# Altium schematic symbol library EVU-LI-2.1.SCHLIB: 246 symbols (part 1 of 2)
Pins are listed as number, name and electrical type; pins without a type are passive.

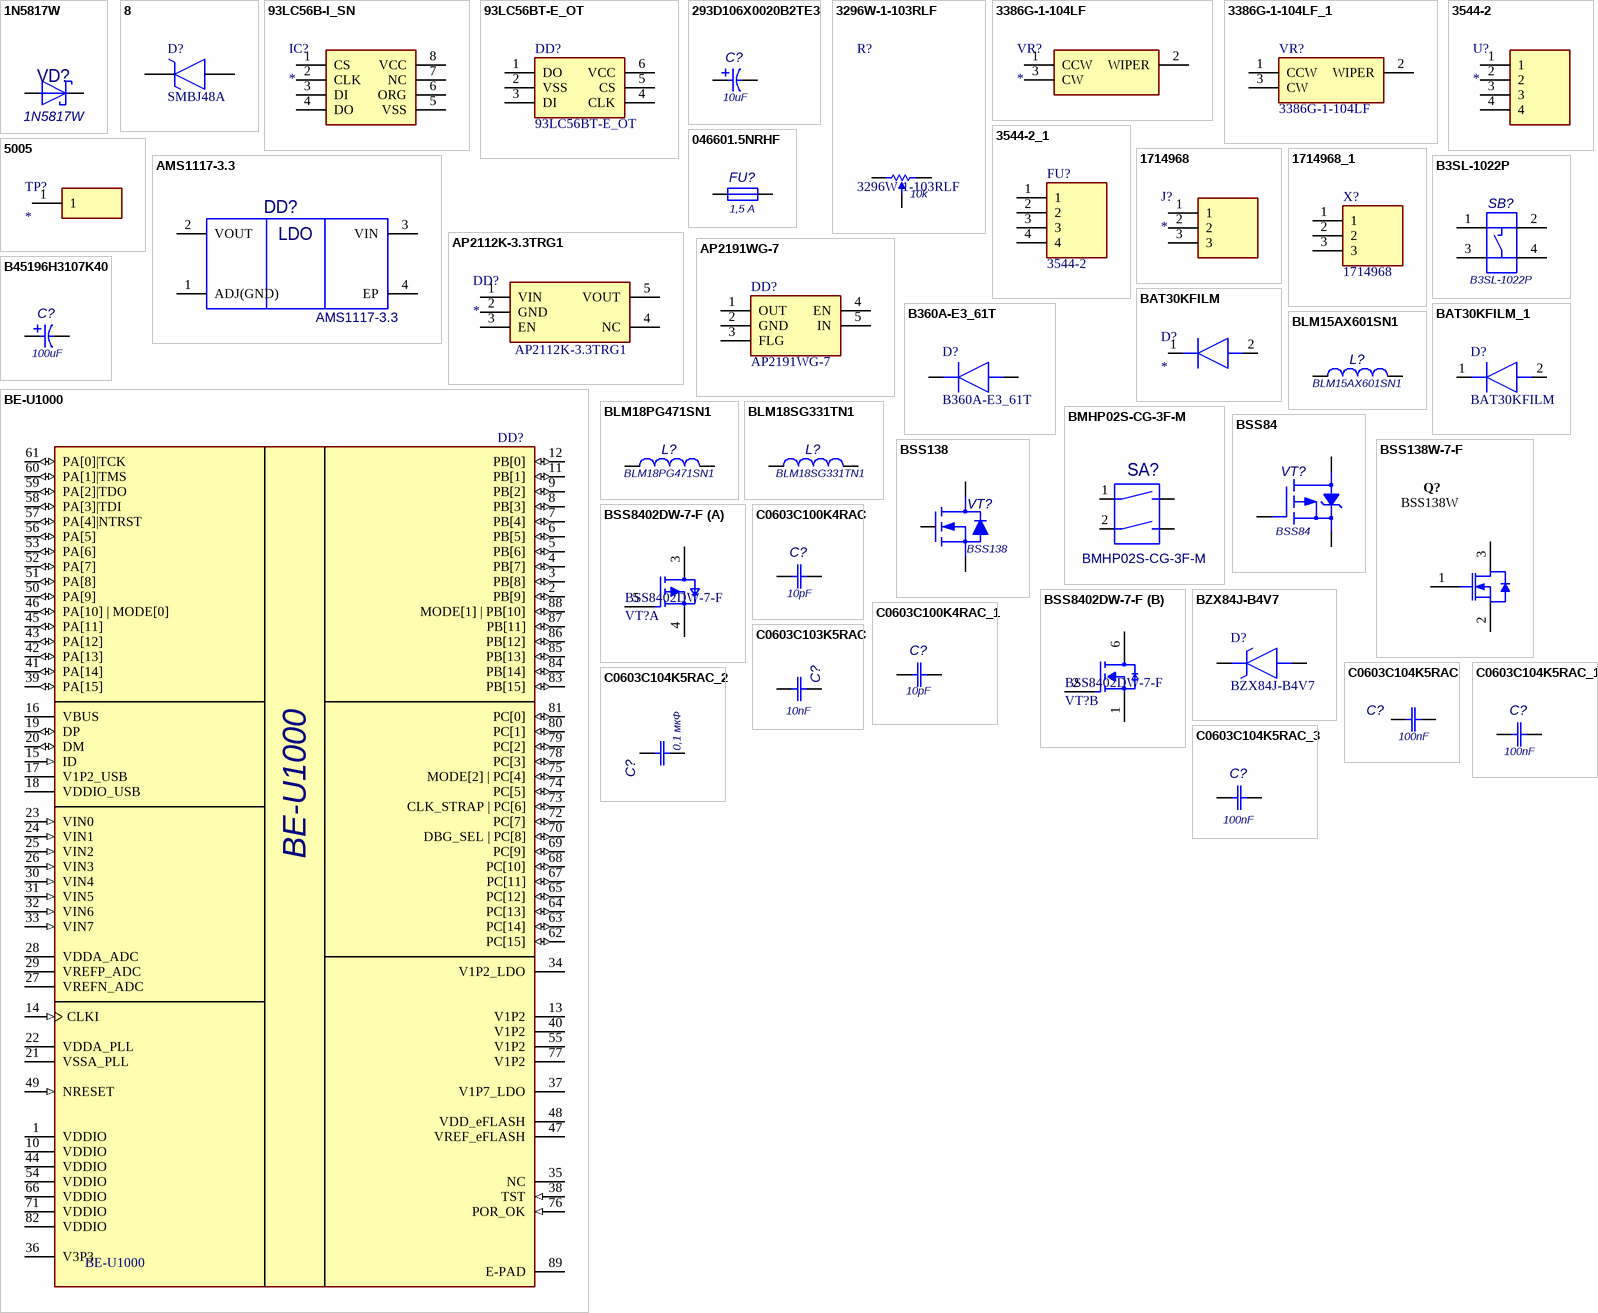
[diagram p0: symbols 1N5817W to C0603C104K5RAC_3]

## 1N5817W
designator VD?
Diode Schottky 20V 1A [SOD-123]; Manufacturer: HOTTECH ELECTRONICS; ESKDname: * 1N5817W, *
footprint DIOD_SMA (Package DO-214AC)
footprint DIOD_SOD-123
footprint DIOD_SOD-123
footprint DIOD_SOD-123W
footprint NSR10F20NXT5G
footprint DIOD_2-XDFN
footprint DIOD_SMF
footprint SOD-323
footprint DIOD_SMB_Flat
footprint DIOD_SMB
pins: A, C

## 8
designator D?, comment SMBJ48A
TVS Diode (Uni-directional); Manufacturer_Name: LITTELFUSE; Manufacturer_Part_Number: SMBJ51A
footprint DIOM5436X261N
footprint Model Name (Footprint not found)
pins: 1 K, 2 A

## 93LC56B-I_SN
designator IC?
Integrated Circuit; Manufacturer_Name: Microchip; Manufacturer_Part_Number: 93LC56B-I/SN
footprint SOIC127P600X175-8N
pins: 1 CS, 2 CLK, 3 DI, 4 DO, 5 VSS, 6 ORG, 7 NC, 8 VCC

## 93LC56BT-E_OT
designator DD?
EEPROM, 2KBIT, SERIAL, 2MHz; Manufacturer_Part_Number: 93LC56BT-E/OT; Manufacturer: "Microchip"; TKE: SOT-23-6
footprint SOT95P270X145-6N
footprint SOT95P280X145-6N
pins: 1 DO, 2 VSS, 3 DI, 4 CLK, 5 CS, 6 VCC

## 293D106X0020B2TE3
designator C?  value 10uF  (hidden comment: 293D106X0020B2TE3)
10uF±20% 20V, Tant type B; Manufacturer: "Vishay"; Tolerance: ±20%; NOM: Type B 10uF ±20% 20V; TKE: Type B; Value Ru: 10мкФ
footprint CAPPM3528X210N
pins: 1, 2

## 3296W-1-103RLF
designator R?  value 10k
Trimmer Resistor 10 kOhms±10% 0,5W; Manufacturer_Name: Bourns; Manufacturer: "Bourns"; Value Ru: 10 кОм; TKE: 3296Y; Power_Voltage: 0,5W; Tolerance: ±10%
footprint 3296W1503LF
footprint 3296W1503LF
pins: 1 CCW, 2 WIPER, 3 CW

## 3386G-1-104LF
designator VR?
Variable Resistor; Manufacturer_Name: Bourns; Manufacturer_Part_Number: 3386G-1-104LF
footprint 3386G1104LF
pins: 1 CCW, 2 WIPER, 3 CW

## 3386G-1-104LF_1
designator VR?, comment 3386G-1-104LF
Variable Resistor; Manufacturer_Name: Bourns
footprint 3386G1104LF
pins: 1 CCW, 2 WIPER, 3 CW

## 3544-2
designator U?
Undefined or Miscellaneous; Manufacturer_Name: Keystone Electronics; Manufacturer_Part_Number: 3544-2
footprint 3544-2
pins: 1, 2, 3, 4

## 3544-2_1
designator FU?, comment 3544-2
Automotive Blade Fuse Holder 20A 500V; Manufacturer: "Keystone Electronics"; Примечание: Fuse Size 2.8mm x 0.8mm
footprint 3544-2
pins: 1, 2, 3, 4

## 5005
designator TP?
Test Point; Manufacturer_Name: Keystone Electronics; Manufacturer_Part_Number: 5005; Manufacturer: "Keystone Electronics"
footprint 5006
pins: 1

## 046601.5NRHF
designator FU?  value 1,5 A  (hidden comment: 046601.5NRHF)
Fuse SMD 1,5A 63V; Manufacturer: "Littelfuse"; MARK: K
footprint FUSE466X32X15X60N
pins: 1, 2

## 1714968
designator J?
Connector; Manufacturer_Name: Phoenix Contact; Manufacturer_Part_Number: 1714968
footprint 1714968
pins: 1, 2, 3

## 1714968_1
designator X?, comment 1714968
PC terminal block, Screw connection, Pitch: 6.35 mm; Manufacturer_Name: Phoenix Contact; Manufacturer: "Phoenix Contact"; Power_Voltage: 500V 30A
footprint 1714968
footprint 1714968
pins: 1, 2, 3

## AMS1117-3.3
designator DD?
1000mA Linear Voltage Regulators; Manufacturer: UMW; ESKDname: Преобразователь напряжения линейный AMS1117-3.3, *
footprint SOT-223
footprint SOT-89 (Small Outline Transistor)
footprint SOT-223
pins: 1 ADJ(GND), 2 VOUT, 3 VIN, 4 EP

## AP2112K-3.3TRG1
designator DD?  Manufacturer_Part_Number: AP2112K-3.3TRG1
LDO voltage regulator; Manufacturer_Name: Diodes Incorporated; Manufacturer: "Diodes"
footprint SOT95P285X140-5N
pins: 1 VIN, 2 GND, 3 EN, 4 NC, 5 VOUT

## AP2191WG-7
designator DD?
Power switch, USB switch, 1.5A; Manufacturer: "Diodes Incorporated"
footprint SOT95P285X140-5N
pins: 1 OUT, 2 GND, 3 FLG, 4 EN, 5 IN

## B3SL-1022P
designator SB?
Surface-mounting Sealed Tactile Switch; Manufacturer: "Omron Corporation"
footprint B3SL-1022P
pins: 1, 2, 3, 4

## B360A-E3_61T
designator D?
Schottky Diode  60V 3.0A; Manufacturer: "Vishay"; Manufacturer_Part_Number: B360A-E3/61T
footprint DIOM5127X229N
pins: 1 K, 2 A

## B45196H3107K40
designator C?  value 100uF  (hidden comment: B45196H3107K40)
100uF±10% 16V, Tant type D; Manufacturer: "Kemet"; Tolerance: ±10%; NOM: Type D 100uF ±10% 16V; TKE: Type D; Value Ru: 100 мкФ
footprint CAPMP7343X190N
pins: 1, 2

## BAT30KFILM
designator D?
Diode; Manufacturer_Name: STMicroelectronics; Manufacturer_Part_Number: BAT30KFILM
footprint SODFL1608X70N
pins: 1 K, 2 A

## BAT30KFILM_1
designator D?, comment BAT30KFILM
Diode; Manufacturer: "STMicroelectronics"; TKE: SOD-523; Power_Voltage: Vrrm 30V Ctyp 14pF if 300mA
footprint SODFL1608X70N
pins: 1 K, 2 A

## BE-U1000
designator DD?
Microcontroller BE-U1000; Manufacturer: "Baikal Electronics"; TKE: QFN 88
footprint QFNWB10X10-88L-AL
pins: 1 VDDIO (power), 2 PB[9] (io), 3 PB[8] (io), 4 PB[7] (io), 5 PB[6] (io), 6 PB[5] (io), 7 PB[4] (io), 8 PB[3] (io), 9 PB[2] (io), 10 VDDIO (power), 11 PB[1] (io), 12 PB[0] (io), 13 V1P2 (power), 14 CLKI (in), 15 ID (in), 16 VBUS (power), 17 V1P2_USB (power), 18 VDDIO_USB (power), 19 DP (io), 20 DM (io), 21 VSSA_PLL (power), 22 VDDA_PLL (power), 23 VIN0 (in), 24 VIN1 (in), 25 VIN2 (in), 26 VIN3 (in), 27 VREFN_ADC (power), 28 VDDA_ADC (power), 29 VREFP_ADC (power), 30 VIN4 (in), 31 VIN5 (in), 32 VIN6 (in), 33 VIN7 (in), 34 V1P2_LDO (power), 35 NC, 36 V3P3 (power), 37 V1P7_LDO (power), 38 TST (in), 39 PA[15] (io), 40 V1P2 (power), 41 PA[14] (io), 42 PA[13] (io), 43 PA[12] (io), 44 VDDIO (power), 45 PA[11] (io), 46 PA[10] | MODE[0] (io), 47 VREF_eFLASH (power), 48 VDD_eFLASH (power), 49 NRESET (in), 50 PA[9] (io), 51 PA[8] (io), 52 PA[7] (io), 53 PA[6] (io), 54 VDDIO (power), 55 V1P2 (power), 56 PA[5] (io), 57 PA[4]|NTRST (io), 58 PA[3]|TDI (io), 59 PA[2]|TDO (io), 60 PA[1]|TMS (io), 61 PA[0]|TCK (io), 62 PC[15] (io), 63 PC[14] (io), 64 PC[13] (io), 65 PC[12] (io), 66 VDDIO (power), 67 PC[11] (io), 68 PC[10] (io), 69 PC[9] (io), 70 DBG_SEL | PC[8] (io), 71 VDDIO (power), 72 PC[7] (io), 73 CLK_STRAP | PC[6] (io), 74 PC[5] (io), 75 MODE[2] | PC[4] (io), 76 POR_OK (in), 77 V1P2 (power), 78 PC[3] (io), 79 PC[2] (io), 80 PC[1] (io), 81 PC[0] (io), 82 VDDIO (power), 83 PB[15] (io), 84 PB[14] (io), 85 PB[13] (io), 86 PB[12] (io), 87 PB[11] (io), 88 MODE[1] | PB[10] (io), 89 E-PAD (power)

## BLM15AX601SN1
designator L?
600 Ohms/100MHz 0,5A 0,34 Ohms; Manufacturer: "Murata"; Value: 600 Ом/100MГц 0,5A 0,34 Ом
footprint BLM15X10X05X50N
pins: 1, 2

## BLM18PG471SN1
designator L?
470 Ohms/100MHz 1A 0,2 Ohms; Manufacturer: "Murata"; Value Ru: 470 Ом/100MГц 1А 0,2 Ом
footprint BLM18X16X08X60N
pins: 1, 2

## BLM18SG331TN1
designator L?
330 Ohms/100 MHz 1,5A 0,07 Ohms; Manufacturer: "Murata"; Value Ru: 330 Ом/100MГц 1,5А 0,07 Ом
footprint INDC1608X95N
pins: 1, 2

## BMHP02S-CG-3F-M
designator SA?
2 switches in case; Manufacturer: "Gangyuan"; ESKDname: Переключатель BMHP02S-CG-3F-M
footprint A6H-21 (SWITCH SMT 2-WAY)
footprint A6H-21 (SWITCH SMT 2-WAY)
pins: 1, 2, 11, 22

## BSS84
designator VT?
P-MOSFET 50V 130mA SOT-23-3; Manufacturer: "NXP Semiconductors"
footprint SOT95P230X110-3N
pins: 1 G, 2 S, 3 D

## BSS138
designator VT?
N-MOSFET 50V 200mA SOT-23-3; Manufacturer: "Fairchild Semiconductor"
footprint SOT95P230X110-3N (Footprint not found)
pins: 1 G, 2 S, 3 D

## BSS138W-7-F
designator Q?, comment BSS138W
N-Channel SIPMOS Small-Signal-Transistor, 60 V VDS, 0.28 A ID, -55 to 150 degC, PG-SOT-323, Reel, Green; Manufacturer: Infineon; Ptot (max): 0.5Â W; RDS (on) (max) (@4.5V): 6,000 mOhm; VDS (max): 60 V; RDS (on) (max): 3,500 mOhm; VGS(th) (max): 1.4Â V; ID (max): 0.28Â A; RthJA (max): 250 K/W; VGS(th) (min): 0.6Â V; IDpuls (max): 1.12Â A; QG: 1 nC; Green: TRUE
footprint INF-PG-SOT-323_M (SOT3, 3-Leads, Body 2x1.25mm, Pitch 0.65mm, IPC Low Density)
footprint INF-PG-SOT-323_N (SOT3, 3-Leads, Body 2x1.25mm, Pitch 0.65mm, IPC Medium Density)
footprint INF-PG-SOT-323_L (SOT3, 3-Leads, Body 2x1.25mm, Pitch 0.65mm, IPC High Density)
pins: 1 GATE, 2 SOURCE, 3 DRAIN

## BSS8402DW-7-F
designator VT?
MOSFET N/P-CH 60V/50V SC70-6; Manufacturer: Diodes; Drain To Source Voltage: 60/-50V; Threshold Vgs Max: 2.5/-2V; Number Of Channels: 2; Turn On Delay Time: 7/10ns; Turn Off Delay Time: 11/18ns; Depletion Mode: False; Number Of P Channels: 1; Transconductance: 0.08/0.05S; Rthja Max: 625°C/W; Gate To Source Voltage: 20V; Power Dissipation: 200mW; Drain To Source Resistance: 4.4/10Ω; Continuous Drain Current: 115/-130mA; Threshold Vgs Min: 1/-0.8V; Max Junction Temp: +150°C; Automotive Grade: NA; Drain To Source Breakdown Voltage: 70/-50V; Standoff Height: 0mm; Pulse Drain Current: 800mA
footprint FP-SOT363-IPC_A
footprint FP-SOT363-IPC_B
footprint FP-SOT363-IPC_C
footprint FP-SOT363-MFG
footprint FP-SOT363-MFG
part A pins: 3 D2, 4 S2, 5 G2
part B pins: 1 S1, 2 G1, 6 D1

## BZX84J-B4V7
designator D?
Zener Diode; Manufacturer: "Nexperia"
footprint SOD2512X80N
pins: 1 K, 2 A

## C0603C100K4RAC
designator C?  Value_ENG: 10pF  (hidden comment: C0603C100K4RAC)
0603 X7R 10 пФ ±10% 16B; Manufacturer: "Kemet"; Value: 10 пФ
footprint CAPC1608X80N
pins: 1, 2

## C0603C100K4RAC_1
designator C?, comment value 10pF  (hidden comment: C0603C100K4RAC)
0603 X7R 10pF±10% 16V; Manufacturer: "Kemet"; Tolerance: ±10%; Power_Voltage: 16B; NOM: 0603 X7R 10pF ±10% 16B; Value Ru: 10 пФ
footprint CAPC1608X80N
pins: 1, 2

## C0603C103K5RAC
designator C?  value 10nF  (hidden comment: C0603C103K5RAC)
0603 X7R 10nF±10% 50V; Manufacturer: "Kemet"; Tolerance: ±10%; Value Ru: 0,01 мкФ
footprint CAPC1608X80N
pins: 1, 2

## C0603C104K5RAC
designator C?  value 100nF  (hidden comment: C0603C104K5RAC)
0603 X7R 0,1 uF ±10% 50V; Manufacturer: "Kemet"; NOM: 0603 X7R 100nF ±10% 50V; Value Ru: 0,1 мкФ
footprint CAPC1608X80N
pins: 1, 2

## C0603C104K5RAC_1
designator C?, comment Value Eng: 100nF  (hidden comment: C0603C104K5RAC)
0603 X7R 0,1 мкФ ±10% 50В; Manufacturer: "Kemet"; Value: 0,1 мкФ
footprint CAPC1608X80N
pins: 1, 2

## C0603C104K5RAC_2
designator C?, comment value 0,1 мкФ  (hidden comment: C0603C104K5RAC)
0603 X7R 0,1 мкФ ±10% 50В; Manufacturer: "Kemet"
footprint CAPC1608X80N
pins: 1, 2

## C0603C104K5RAC_3
designator C?, comment value 100nF  (hidden comment: C0603C104K5RAC)
0603 X7R 0,1uF±10% 50V; Manufacturer: "Kemet"; Tolerance: ±10%; NOM: 0603 X7R 100nF ±10% 50V; Value Ru: 0,1 мкФ
footprint CAPC1608X80N
pins: 1, 2

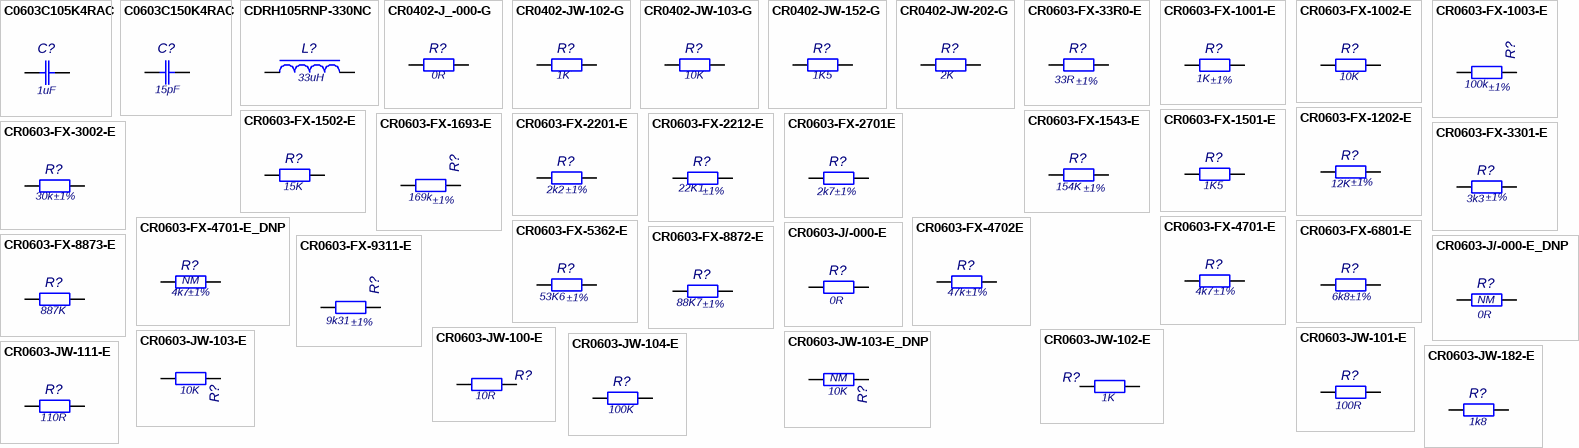
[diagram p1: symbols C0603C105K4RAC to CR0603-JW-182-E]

## C0603C105K4RAC
designator C?  value 1uF  (hidden comment: C0603C105K4RAC)
0603 X7R 1uF±10% 16V; Manufacturer: "Kemet"; Tolerance: ±10%; Value Ru: 1 мкФ
footprint CAPC1608X80N
pins: 1, 2

## C0603C150K4RAC
designator C?  value 15pF  (hidden comment: C0603C150K4RAC)
0603 X7R 15pF±10% 16V; ManufacturerPartNumber: C0603C100K4RAC; Manufacturer: "Kemet"; Tolerance: ±10%; Value Ru: 15 пФ; Replacement: 06035A150JAT2A
footprint CAPC1608X80N
pins: 1, 2

## CDRH105RNP-330NC
designator L?  Value Eng: 33uH  (hidden comment: CDRH105RNP-330NC)
33 uH±30% 2.75A 65mOhm SMD; Manufacturer: "Sumida"; Power_Voltage: 2,4 A; NOM: 33 мкГн  2,4 A; Value: 33 мкГн
footprint CDRH105RNP
pins: 1, 2

## CR0402-J_-000-G
designator R?  value 0R  (hidden comment: CR0402-J_-000-G)
04023 0 Ohm 0.063W; ManufacturerPartNumber: CR0402-J/-000-G; Manufacturer: "Bourns"; Power_Voltage: 0,0625 Вт; MARK: 0; TKE: 0402; NOM: 0402 0R  0,0625 Вт; Value RU: 0 Ом
footprint RESC1005X35N
footprint RESC1005X35N
pins: 1, 2

## CR0402-JW-102-G
designator R?  value 1K  (hidden comment: CR0402-JW-102-G)
0402 1 kOhm ±1% 0.063W; Manufacturer: "Bourns"; Power_Voltage: 0,0625 W; MARK: 102; TKE: 0402; NOM: 0402 1K ±5% 0,0625 W; Tolerance: ±5%; Value Ru: 1 кОм
footprint RESC1005X35N
pins: 1, 2

## CR0402-JW-103-G
designator R?  value 10K  (hidden comment: CR0402-JW-103-G)
0402 10 kOhm ±1% 0.063W; Manufacturer: "Bourns"; Power_Voltage: 0,0625 W; MARK: 103; TKE: 0402; NOM: 0402 10K ±5% 0,0625 W; Tolerance: ±5%; Value Ru: 10 кОм
footprint RESC1005X35N
pins: 1, 2

## CR0402-JW-152-G
designator R?  value 1K5  (hidden comment: CR0402-JW-152-G)
0402 1.5 kOhm ±1% 0.063W; Manufacturer: "Bourns"; Power_Voltage: 0,0625 W; MARK: 152; TKE: 0402; NOM: 0402 1K5 ±5% 0,0625 W; Tolerance: ±5%; Value Ru: 1,5 кОм
footprint RESC1005X35N
pins: 1, 2

## CR0402-JW-202-G
designator R?  value 2K  (hidden comment: CR0402-JW-202-G)
0402 2 kOhm±5% 0.063W; Manufacturer: "Bourns"; Power_Voltage: 0,0625 W; MARK: 202; TKE: 0402; NOM: 0402 2K ±5% 0,0625 W; Tolerance: ±5%; Value Ru: 2 кОм
footprint RESC1005X35N
pins: 1, 2

## CR0603-FX-33R0-E
designator R?  value 33R  Tolerance: ±1%  (hidden comment: CR0603-FX-33R0-E)
0603 33 Ohm±1% 0,1W; Manufacturer: "Bourns"; TKE: 0603; Power_Voltage: 0,1W; NOM: 0603 33R ±1% 0,1W; Value Ru: 33 Ом
footprint RESC1608X45N
pins: 1, 2

## CR0603-FX-1001-E
designator R?  value 1K  Tolerance: ±1%  (hidden comment: CR0603-FX-1001-E)
0603 1 kOhm±1% 0,1W; Manufacturer: "Bourns"; TKE: 0603; MARK: 01B; Power_Voltage: 0,1W; NOM: 0603 1K ±1% 0,1W; Value Ru: 1 кОм
footprint RESC1608X45N
pins: 1, 2

## CR0603-FX-1002-E
designator R?  value 10K  (hidden comment: CR0603-FX-1002-E)
0603 10 kOm±1% 0,1W; Manufacturer: "Bourns"; TKE: 0603; MARK: 01C; Power_Voltage: 0,1 Вт; NOM: 0603 10K ±1% 0,1 Вт; Value Ru: 10 кОм; Tolerance: ±1%
footprint RESC1608X45N
pins: 1, 2

## CR0603-FX-1003-E
designator R?  value 100k  Tolerance: ±1%  (hidden comment: CR0603-FX-1003-E)
0603 100 kOhm±1% 0,1W; ManufacturerPartNumber: CR0603-FX-1693-E; Manufacturer: "Bourns"; TKE: 0603; MARK: 23D; Power_Voltage: 0,1W; NOM: 0603 100k ±1% 0,1W; Value Ru: 100 кОм
footprint RESC1608X45N
pins: 1, 2

## CR0603-FX-1202-E
designator R?  value 12K  Tolerance: ±1%  (hidden comment: CR0603-FX-1202-E)
0603 12 kOhm±1% 0,1W; ManufacturerPartNumber: CR0603-JW-123-E; Manufacturer: "Bourns"; TKE: 0603; MARK: 123; Power_Voltage: 0,1 Вт; NOM: 0603 12K ±1% 0,1 Вт; Value Ru: 12 кОм
footprint RESC1608X45N
pins: 1, 2

## CR0603-FX-1501-E
designator R?  value 1K5  (hidden comment: CR0603-FX-1501-E)
0603 1.5 kOm ±1% 0,1W; Manufacturer: "Bourns"; TKE: 0603; MARK: 18C; Power_Voltage: 0,1 Вт; NOM: 0603 1K5 ±1% 0,1 Вт; Value Ru: 1.5 кОм
footprint RESC1608X45N
pins: 1, 2

## CR0603-FX-1502-E
designator R?  value 15K  (hidden comment: CR0603-FX-1502-E)
0603 15 kOm ±1% 0,1W; Manufacturer: "Bourns"; TKE: 0603; MARK: 18C; Power_Voltage: 0,1 Вт; NOM: 0603 15K ±1% 0,1 Вт; Value Ru: 15 кОм
footprint RESC1608X45N
pins: 1, 2

## CR0603-FX-1543-E
designator R?  value 154K  Tolerance: ±1%  (hidden comment: CR0603-FX-1543-E)
0603 154 kOhm±1% 0,1W; Manufacturer: "Bourns"; TKE: 0603; MARK: 19D; Power_Voltage: 0,1 Вт; NOM: 0603 154K ±1% 0,1 Вт; Value Ru: 154 кОм
footprint RESC1608X45N
pins: 1, 2

## CR0603-FX-1693-E
designator R?  Value Eng: 169k  Tolerance: ±1%  (hidden comment: CR0603-FX-1693-E)
169 кОм ±1%; Manufacturer: "Bourns"; TKE: 0603; MARK: 23D; Power_Voltage: 0,1 Вт; NOM: 0603 169 кОм ±1% 0,1 Вт; Value: 169 кОм
footprint RESC1608X45N
pins: 1, 2

## CR0603-FX-2201-E
designator R?  value 2k2  Tolerance: ±1%  (hidden comment: CR0603-FX-2201-E)
2k2±1%; Manufacturer: "Bourns"; TKE: 0603; MARK: 222; Power_Voltage: 0,1 Вт; NOM: 0603 2k2 ±1% 0,1 Вт; Value Ru: 2,2 кОм
footprint RESC1608X45N
pins: 1, 2

## CR0603-FX-2212-E
designator R?  value 22K1  Tolerance: ±1%  (hidden comment: CR0603-FX-2212-E)
0603 22,1 kOhm±1% 0,1W; Manufacturer: "Bourns"; TKE: 0603; MARK: 34C; Power_Voltage: 0,1 Вт; NOM: 0603 22K1 ±1% 0,1 Вт; Value Ru: 22,1 кОм
footprint RESC1608X45N
pins: 1, 2

## CR0603-FX-2701E
designator R?  value 2k7  Tolerance: ±1%  (hidden comment: CR0603-FX-2701E)
2k7±1%; Manufacturer: "Bourns"; TKE: 0603; Power_Voltage: 0,1W; NOM: 0603 2k7 ±1% 0,1W; Value Ru: 2,7 кОм
footprint RESC1608X45N
pins: 1, 2

## CR0603-FX-3002-E
designator R?  value 30k  Tolerance: ±1%  (hidden comment: CR0603-FX-3002-E)
0603 30 kOhm±1% 0,1W; Manufacturer: "Bourns"; TKE: 0603; Power_Voltage: 0,1W; NOM: 0603 30k ±1% 0,1W; Value Ru: 30 кОм
footprint RESC1608X45N
pins: 1, 2

## CR0603-FX-3301-E
designator R?  value 3k3  Tolerance: ±1%  (hidden comment: CR0603-FX-3301-E)
0603 3,3 kOhm±1% 0,1W; Manufacturer: "Bourns"; TKE: 0603; Power_Voltage: 0,1W; NOM: 0603 3k3 ±1% 0,1W; Value Ru: 3,3 кОм
footprint RESC1608X45N
pins: 1, 2

## CR0603-FX-4701-E
designator R?  value 4k7  Tolerance: ±1%  (hidden comment: CR0603-FX-4701-E)
0603 4,7 kOhm±1% 0,1W; Manufacturer: "Bourns"; TKE: 0603; Power_Voltage: 0,1W; NOM: 0603 4k7 ±1% 0,1W; Value Ru: 4,7 кОм
footprint RESC1608X45N
pins: 1, 2

## CR0603-FX-4701-E_DNP
designator R?, comment value 4k7  Примечание: NM  Tolerance: ±1%  (hidden comment: CR0603-FX-4701-E)
0603 4,7 kOhm±1% 0,1W; Manufacturer: "Bourns"; TKE: 0603; Power_Voltage: 0,1W; NOM: 0603 4k7 ±1% 0,1W; Value Ru: 4,7 кОм
footprint RESC1608X45N
pins: 1, 2

## CR0603-FX-4702E
designator R?  value 47k  Tolerance: ±1%  (hidden comment: CR0603-FX-4702E)
47kOm±1%; Manufacturer: "Bourns"; TKE: 0603; Power_Voltage: 0,1W; NOM: 0603 47k ±1% 0,1W; Value Ru: 47 кОм
footprint RESC1608X45N
pins: 1, 2

## CR0603-FX-5362-E
designator R?  value 53K6  Tolerance: ±1%  (hidden comment: CR0603-FX-5362-E)
0603 53,6 kOhm ±1% 0,1W; Manufacturer: "Bourns"; TKE: 0603; Power_Voltage: 0,1W; NOM: 0603 53K6 ±1% 0,1W; Value Ru: 53,6 кОм
footprint RESC1608X45N
pins: 1, 2

## CR0603-FX-6801-E
designator R?  value 6k8  Tolerance: ±1%  (hidden comment: CR0603-FX-6801-E)
6k8±1%; Manufacturer: "Bourns"; TKE: 0603; Power_Voltage: 0,1W; NOM: 0603 6k8 ±1% 0,1W; Value Ru: 6,8 кОм
footprint RESC1608X45N
pins: 1, 2

## CR0603-FX-8872-E
designator R?  value 88K7  Tolerance: ±1%  (hidden comment: CR0603-FX-8872-E)
0603 88,7 kOhm±1% 0,1W; Manufacturer: "Bourns"; TKE: 0603; Power_Voltage: 0,1W; NOM: 0603 88K7 ±1% 0,1W; Value Ru: 88,7 кОм
footprint RESC1608X45N
pins: 1, 2

## CR0603-FX-8873-E
designator R?  value 887K  (hidden comment: CR0603-FX-8873-E)
0603 887 kOm ±1% 0,1W; Manufacturer: "Bourns"; TKE: 0603; MARK: 92D; Power_Voltage: 0,1 Вт; NOM: 0603 887K ±1% 0,1 Вт; Value Ru: 887 кОм
footprint RESC1608X45N
pins: 1, 2

## CR0603-FX-9311-E
designator R?  Value Eng: 9k31  Tolerance: ±1%  (hidden comment: CR0603-FX-9311-E)
9,31 кОм ±1%; Manufacturer: "Bourns"; TKE: 0603; MARK: 94B; Power_Voltage: 0,1 Вт; NOM: 0603 9,31 кОм ±1% 0,1 Вт
footprint RESC1608X45N
pins: 1, 2

## CR0603-J/-000-E
designator R?  value 0R  (hidden comment: CR0603-J/-000-E)
0603 0 Ohm 0,1W; Manufacturer: "Bourns"; TKE: 0603; MARK: 000; NOM: 0603 0R; Value Ru: 0 Ом; Replacement: RC0603JR-070RL
footprint RESC1608X45N
pins: 1, 2

## CR0603-J/-000-E_DNP
designator R?, comment value 0R  Примечание: NM  (hidden comment: CR0603-J/-000-E)
0603 0 Ohm 0,1W; Manufacturer: "Bourns"; TKE: 0603; MARK: 000; NOM: 0603 0R; Value Ru: 0 Ом
footprint RESC1608X45N
pins: 1, 2

## CR0603-JW-100-E
designator R?  value 10R  (hidden comment: CR0603-JW-100-E)
0603 10 Ohm±5% 0.1W; Manufacturer: "Bourns"; TKE: 0603; MARK: 100; Power_Voltage: 0,1W; NOM: 0603 10R ±5% 0,1W; Tolerance: ±5%; Value Ru: 10 Ом; DNP: NM
footprint RESC1608X45N
pins: 1, 2

## CR0603-JW-101-E
designator R?  value 100R  (hidden comment: CR0603-JW-101-E)
0603 100 Ohm±5% 0,1W; Manufacturer: "Bourns"; TKE: 0603; MARK: 101; Power_Voltage: 0,1W; NOM: 0603 100R ±5% 0,1W; Tolerance: ±5%; Value Ru: 100 Ом
footprint RESC1608X45N
pins: 1, 2

## CR0603-JW-102-E
designator R?  Value Eng: 1K  (hidden comment: CR0603-JW-102-E)
1 кОм , 1K; Manufacturer: "Bourns"; TKE: 0603; MARK: 102; Power_Voltage: 0,1 Вт; NOM: 0603 1 кОм ±5% 0,1 Вт; Tolerance: ±5%; Value: 1 кОм
footprint RESC1608X45N
pins: 1, 2

## CR0603-JW-103-E
designator R?  value 10K  (hidden comment: CR0603-JW-103-E)
0603 10 kOhm±5% 0,1W; Manufacturer: "Bourns"; TKE: 0603; MARK: 103; Power_Voltage: 0,1W; NOM: 0603 10K ±5% 0,1W; Tolerance: ±5%; Value Ru: 10 кОм
footprint RESC1608X45N
pins: 1, 2

## CR0603-JW-103-E_DNP
designator R?, comment value 10K  Примечание: NM  (hidden comment: CR0603-JW-103-E)
0603 10 kOhm±5% 0,1W; Manufacturer: "Bourns"; TKE: 0603; MARK: 103; Power_Voltage: 0,1W; NOM: 0603 10K ±5% 0,1W; Tolerance: ±5%; Value Ru: 10 кОм
footprint RESC1608X45N
pins: 1, 2

## CR0603-JW-104-E
designator R?  value 100K  (hidden comment: CR0603-JW-104-E)
0603 100 kOhm±5% 0.1W; Manufacturer: "Bourns"; TKE: 0603; MARK: 104; Power_Voltage: 0,1 Вт; NOM: 0603 100K ±5% 0,1 Вт; Tolerance: ±5%; Value Ru: 100 кОм
footprint RESC1608X45N
pins: 1, 2

## CR0603-JW-111-E
designator R?  Value Eng: 110R  (hidden comment: CR0603-JW-111-E)
110 Ом , 110R; Manufacturer: "Bourns"; TKE: 0603; MARK: 111; Power_Voltage: 0,1 Вт; NOM: 0603 110 Ом ±5% 0,1 Вт; Tolerance: ±5%; Value: 110 Ом
footprint RESC1608X45N
pins: 1, 2

## CR0603-JW-182-E
designator R?  value 1k8  (hidden comment: CR0603-JW-182-E)
0603 1,8 kOhm±5% 0,1W; Manufacturer: "Bourns"; TKE: 0603; MARK: 182; Power_Voltage: 0,1 Вт; NOM: 0603 1k8 ±5% 0,1 Вт; Tolerance: ±5%; Value Ru: 1,8 кОм
footprint RESC1608X45N
pins: 1, 2

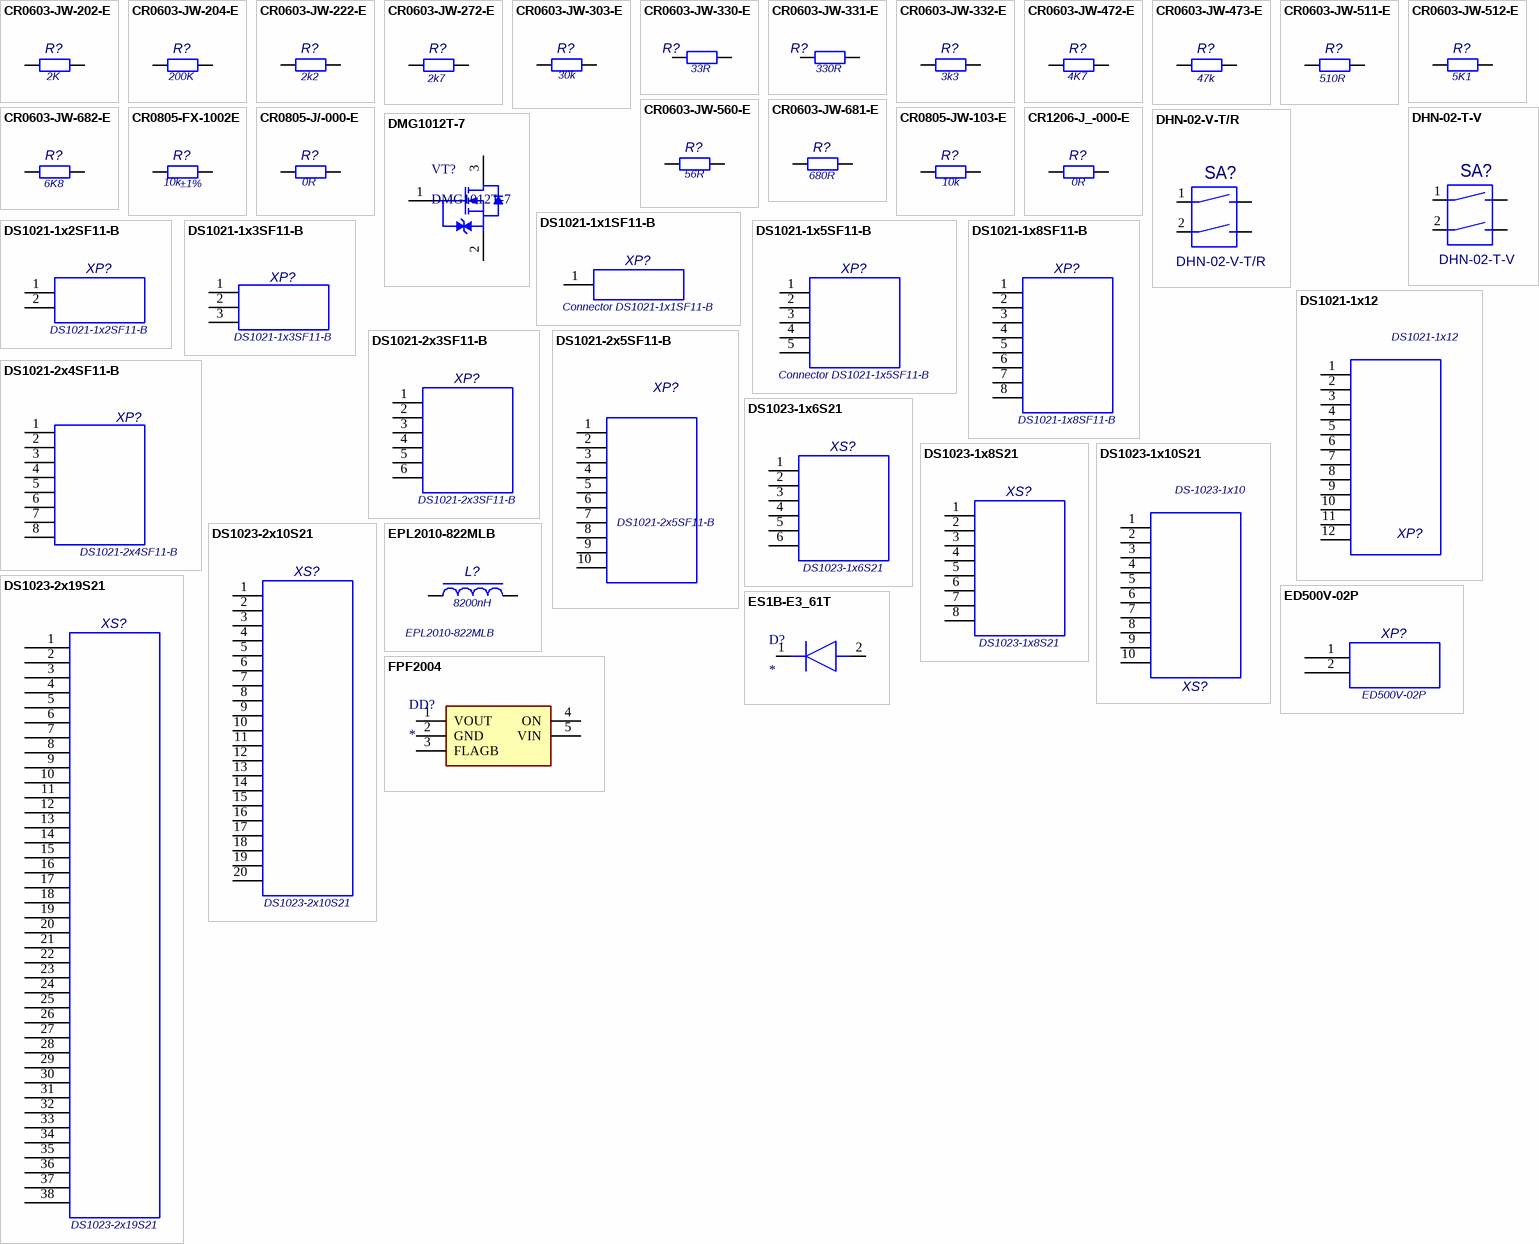
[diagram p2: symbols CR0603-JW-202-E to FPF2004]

## CR0603-JW-202-E
designator R?  value 2K  (hidden comment: CR0603-JW-202-E)
0603 2 kOhm±5% 0.1W; Manufacturer: "Bourns"; TKE: 0603; MARK: 202; Power_Voltage: 0,1 Вт; NOM: 0603 2K ±5% 0,1 Вт; Tolerance: ±5%; Value Ru: 2 кОм
footprint RESC1608X45N
pins: 1, 2

## CR0603-JW-204-E
designator R?  value 200K  (hidden comment: CR0603-JW-204-E)
0603 200 kOm±5% 0.1W; Manufacturer: "Bourns"; TKE: 0603; MARK: 204; Power_Voltage: 0,1 Вт; NOM: 0603 200K ±5% 0,1 Вт; Tolerance: ±5%; Value Ru: 200 кОм
footprint RESC1608X45N
pins: 1, 2

## CR0603-JW-222-E
designator R?  Value Eng: 2k2  (hidden comment: CR0603-JW-222-E)
0603 2,2 kOhm±5% 0,1W; Manufacturer: "Bourns"; TKE: 0603; MARK: 222; Power_Voltage: 0,1W; NOM: 0603 2,2 кОм ±5% 0,1W; Tolerance: ±5%; Value: 2,2 кОм
footprint RESC1608X45N
pins: 1, 2

## CR0603-JW-272-E
designator R?  Value Eng: 2k7  (hidden comment: CR0603-JW-272-E)
0603 2,7 kOhm±5% 0,1W; Manufacturer: "Bourns"; TKE: 0603; MARK: 272; Power_Voltage: 0,1 Вт; NOM: 0603 2,7 кОм ±5% 0,1 Вт; Tolerance: ±5%; Value: 2,7 кОм
footprint RESC1608X45N
pins: 1, 2

## CR0603-JW-303-E
designator R?  Value Eng: 30k  (hidden comment: CR0603-JW-303-E)
0603 30 kOhm±5% 0,1W; Manufacturer: "Bourns"; TKE: 0603; MARK: 303; Power_Voltage: 0,1 Вт; NOM: 0603 30 кОм ±5% 0,1 Вт; Tolerance: ±5%; Value: 30 кОм
footprint RESC1608X45N
pins: 1, 2

## CR0603-JW-330-E
designator R?  value 33R  (hidden comment: CR0603-JW-330-E)
0603 33 Om ±5% 0.1W; Manufacturer: "Bourns"; TKE: 0603; MARK: 330; Power_Voltage: 0,1 Вт; NOM: 0603 33R ±5% 0,1 Вт; Value Ru: 33 Ом
footprint RESC1608X45N
pins: 1, 2

## CR0603-JW-331-E
designator R?  value 330R  (hidden comment: CR0603-JW-331-E)
0603 330 Om ±5% 0.1W; Manufacturer: "Bourns"; TKE: 0603; MARK: 330; Power_Voltage: 0,1 Вт; NOM: 0603 330R ±5% 0,1 Вт; Value Ru: 330 Ом
footprint RESC1608X45N
pins: 1, 2

## CR0603-JW-332-E
designator R?  Value Eng: 3k3  (hidden comment: CR0603-JW-332-E)
3.3 кОм 3k3; Manufacturer: "Bourns"; TKE: 0603; MARK: 332; Power_Voltage: 0,1 Вт; NOM: 0603 3,3 кОм ±5% 0,1 Вт; Tolerance: ±5%; Value: 3,3 кОм
footprint RESC1608X45N
pins: 1, 2

## CR0603-JW-472-E
designator R?  value 4K7  (hidden comment: CR0603-JW-472-E)
0603 4,7 kOm±5% 0.1W; Manufacturer: "Bourns"; TKE: 0603; MARK: 472; Power_Voltage: 0,1 Вт; NOM: 0603 4K7 ±5% 0,1 Вт; Tolerance: ±5%; Value Ru: 4,7 кОм
footprint RESC1608X45N
pins: 1, 2

## CR0603-JW-473-E
designator R?  Value Eng: 47k  (hidden comment: CR0603-JW-473-E)
0603 47 kOhms±5% 0,1W; Manufacturer: "Bourns"; TKE: 0603; MARK: 473; Power_Voltage: 0,1 Вт; NOM: 0603 47 кОм ±5% 0,1 Вт; Tolerance: ±5%; Value: 47 кОм
footprint RESC1608X45N
pins: 1, 2

## CR0603-JW-511-E
designator R?  Value Eng: 510R  (hidden comment: CR0603-JW-511-E)
0603 510 Om ±5% 0.1W; Manufacturer: "Bourns"; TKE: 0603; MARK: 511; Power_Voltage: 0,1 Вт; NOM: 0603 510 Ом ±5% 0,1 Вт; Value: 510 Ом
footprint RESC1608X45N
pins: 1, 2

## CR0603-JW-512-E
designator R?  Value Eng: 5K1  (hidden comment: CR0603-JW-512-E)
0603 5,1 kOhm±5% 0,1W; ManufacturerPartNumber: CR0603-JW-682-E; Manufacturer: "Bourns"; TKE: 0603; MARK: 512; Power_Voltage: 0,1 Вт; NOM: 0603 5,1 кОм ±5% 0,1 Вт; Tolerance: ±5%; Value: 5,1 кОм
footprint RESC1608X45N
pins: 1, 2

## CR0603-JW-560-E
designator R?  value 56R  (hidden comment: CR0603-JW-560-E)
0603 56 Ohm±5% 0,1W; Manufacturer: "Bourns"; TKE: 0603; MARK: 560; Power_Voltage: 0,1W; NOM: 0603 56R ±5% 0,1W; Tolerance: ±5%; Value Ru: 56 Ом
footprint RESC1608X45N
pins: 1, 2

## CR0603-JW-681-E
designator R?  value 680R  (hidden comment: CR0603-JW-681-E)
0603 680 Ohm±5% 0,1W; Manufacturer: "Bourns"; TKE: 0603; MARK: 681; Power_Voltage: 0,1W; NOM: 0603 680R ±5% 0,1W; Tolerance: ±5%; Value Ru: 680 Ом
footprint RESC1608X45N
pins: 1, 2

## CR0603-JW-682-E
designator R?  value 6K8  (hidden comment: CR0603-JW-682-E)
0603 6,8 kOhm±5% 0,1W; Manufacturer: "Bourns"; TKE: 0603; MARK: 682; Power_Voltage: 0,1 Вт; NOM: 0603 6K8 ±5% 0,1 Вт; Tolerance: ±5%; Value Ru: 6,8 кОм
footprint RESC1608X45N
pins: 1, 2

## CR0805-FX-1002E
designator R?  value 10k  Tolerance: ±1%  (hidden comment: CR0805-FX-1002E)
10k±1%; ManufacturerPartNumber: CR0805-JW-103-E; Manufacturer: "Bourns"; TKE: 0805; MARK: 103; Power_Voltage: 0,1 Вт; NOM: 0805 10k ±1% 0,1 Вт; Value Ru: 10 кОм
footprint RESC2012X50N
pins: 1, 2

## CR0805-J/-000-E
designator R?  value 0R  (hidden comment: CR0805-J/-000-E)
0805 0 Ohm 0,1W; Manufacturer: "Bourns"; TKE: 0805; MARK: 000; Power_Voltage: 0,1W; NOM: 0805 0R  0,1W; Value Ru: 0 Ом; DNP: NM
footprint RESC2012X50N
pins: 1, 2

## CR0805-JW-103-E
designator R?  Value Eng: 10k  (hidden comment: CR0805-JW-103-E)
0805 10 kOhm±5% 0,1W; Manufacturer: "Bourns"; TKE: 0805; MARK: 103; Power_Voltage: 0,1W; NOM: 0805 10 кОм ±5% 0,1W; Tolerance: ±5%; Value: 10 кОм
footprint RESC2012X50N
pins: 1, 2

## CR1206-J_-000-E
designator R?  Value Eng: 0R  (hidden comment: CR1206-J_-000-E)
0 Ом 0R; ManufacturerPartNumber: CR1206-J/-000; Manufacturer: "Bourns"; TKE: 1206; MARK: 0; NOM: 1206 0 Ом; Value: 0 Ом
footprint RESC3216X75N
pins: 1, 2

## DHN-02-T-V
designator SA?
2 switches in case; Manufacturer: "DIPTRONICS"; ESKDname: Переключатель DHN-02-T-V
footprint A6H-21 (SWITCH SMT 2-WAY)
pins: 1, 2, 11, 22

## DHN-02-V-T/R
designator SA?
2 switches in case; Manufacturer: "DIPTRONICS"; ESKDname: Переключатель DHN-02-V-T/R
footprint A6H-21 (SWITCH SMT 2-WAY)
pins: 1, 2, 11, 22

## DMG1012T-7
designator VT?
N-Channel Enhancement Mode MOSFET, 20 V, 630 mA, -55 to 150 degC, 3-Pin SOT23, RoHS, Tape and Reel; Manufacturer: Diodes Inc; Continuous Drain Current (ID): 630mA; Number of Channels: 1; Drain to Source Voltage (Vdss): 20V; Gate to Source Voltage (Vgs): 6V; Turn-On Delay Time: 5.1ns; Rds On Max: 400mOhm; Power Dissipation: 280mW; Fall Time: 12.3ns; Input Capacitance: 60.67pF; Turn-Off Delay Time: 26.7ns; Rise Time: 7.4ns; Drain to Source Resistance: 300mOhm; Element Configuration: Single; Case\/Package: SOT-523; Threshold Voltage: 1V
footprint DIOD-SOT523-3_V (SOT523, 3-Leads, Body 1.6x0.8mm, Pitch 0.50mm)
pins: 1 G, 2 S, 3 D

## DS1021-1x1SF11-B
designator XP?, comment Connector DS1021-1x1SF11-B
2.54 pitch, 1 rows, 8.54 height; Manufacturer: "Connfly"
footprint PLS-1
pins: 1

## DS1021-1x2SF11-B
designator XP?
Connector 2.54 pitch, 1 rows, 8.54 height; Manufacturer: "Connfly"; DNP: NM
footprint PLS2-254PX50X25X854N
pins: 1, 2

## DS1021-1x3SF11-B
designator XP?
Connector 2.54 pitch, 1 rows, 8.54 height; Manufacturer: "Connfly"
footprint PLS3-254PX76X25X854N
pins: 1, 2, 3

## DS1021-1x5SF11-B
designator XP?, comment Connector DS1021-1x5SF11-B
Connector 2.54 pitch, 1 rows, 8.54 height; Manufacturer: "Connfly"
footprint PLS5-254PX127X25X854N
pins: 1, 2, 3, 4, 5

## DS1021-1x8SF11-B
designator XP?
Connector 2.54 pitch, 1 rows, 8.54 height; Manufacturer: "Connfly"
footprint PLS8-254PX200X25X854N
pins: 1, 2, 3, 4, 5, 6, 7, 8

## DS1021-1x12
designator XP?
Connector 2.54 pitch, 1 rows, 8.54 height; ManufacturerPartNumber: DS1021-1x12 (PLS-12); Manufacturer: "Connfly"
footprint PLS-12 (Pin Header, 2.54mm pitch)
pins: 1, 2, 3, 4, 5, 6, 7, 8, 9, 10, 11, 12

## DS1021-2x3SF11-B
designator XP?
Connector 2.54 pitch, 2 rows, 8.54 height; Manufacturer: "Connfly"
footprint PLD6-254PX762X508X854N
pins: 1, 2, 3, 4, 5, 6

## DS1021-2x4SF11-B
designator XP?
Connector 2.54 pitch, 1 rows, 8.54 height; Manufacturer: "Connfly"
footprint PLD8-254PX1001X254X854N
pins: 1, 2, 3, 4, 5, 6, 7, 8

## DS1021-2x5SF11-B
designator XP?
Connector 2.54 pitch, 1 rows, 8.54 height; Manufacturer: "Connfly"
footprint PLD10-254PX1278X254X854N
pins: 1, 2, 3, 4, 5, 6, 7, 8, 9, 10

## DS1023-1x6S21
designator XS?
Connector 2.54 pitch, 1 rows, 8.54 height; ManufacturerPartNumber: DS1023-1x6S21(PBS-6); Manufacturer: "Connfly"
footprint PBS6-254PX152X25X840N - duplicate
pins: 1, 2, 3, 4, 5, 6

## DS1023-1x8S21
designator XS?
Connector 2.54 pitch, 1 rows, 8.54 height; ManufacturerPartNumber: DS-1023-1x8 (PBS-8); Manufacturer: "Connfly"
footprint PBS8-254PX200X25X840N - duplicate
pins: 1, 2, 3, 4, 5, 6, 7, 8

## DS1023-1x10S21
designator XS?, comment DS-1023-1x10
Connector 2.54 pitch, 1 rows, 8.54 height; ManufacturerPartNumber: DS1023-1X10S21 (PBS-10); Manufacturer: "Connfly"
footprint PBS10-254PX152X25X840N - duplicate
pins: 1, 2, 3, 4, 5, 6, 7, 8, 9, 10

## DS1023-2x10S21
designator XS?
2.54 pitch, 2 rows, 8.54 height; Manufacturer: "Connfly"
footprint DS1023210SF11
pins: 1, 2, 3, 4, 5, 6, 7, 8, 9, 10, 11, 12, 13, 14, 15, 16, 17, 18, 19, 20

## DS1023-2x19S21
designator XS?
2.54 pitch, 2 rows, 8.54 height; Manufacturer: "Connfly"
footprint DS1023219SF11
pins: 1, 2, 3, 4, 5, 6, 7, 8, 9, 10, 11, 12, 13, 14, 15, 16, 17, 18, 19, 20, 21, 22, 23, 24, 25, 26, 27, 28, 29, 30, 31, 32, 33, 34, 35, 36, 37, 38

## ED500V-02P
designator XP?
Wire protector type terminal blocks, 5.0 pitch*2; Manufacturer: "Dinkle Enterprise"
footprint ED500V-02P
pins: 1, 2

## EPL2010-822MLB
designator L?  Vaalue Eng: 8200nH
8,2 мкГн 0,52 A; ManufacturerPartNumber: IFSC1515AHER8R2M01; Manufacturer: "Vishay"; Power_Voltage: 1,4 A; NOM: 8,2 мкГн  1,4 A
footprint EPL2010822MLB
pins: 1, 2

## ES1B-E3_61T
designator D?
Diode; Manufacturer_Name: Vishay; Manufacturer_Part_Number: ES1B-E3/61T
footprint DIOM5127X229N
pins: 1 K, 2 A

## FPF2004
designator DD?
Integrated Circuit; Manufacturer_Name: onsemi; Manufacturer_Part_Number: FPF2004
footprint SOT65P210X110-5N
pins: 1 VOUT, 2 GND, 3 FLAGB, 4 ON, 5 VIN

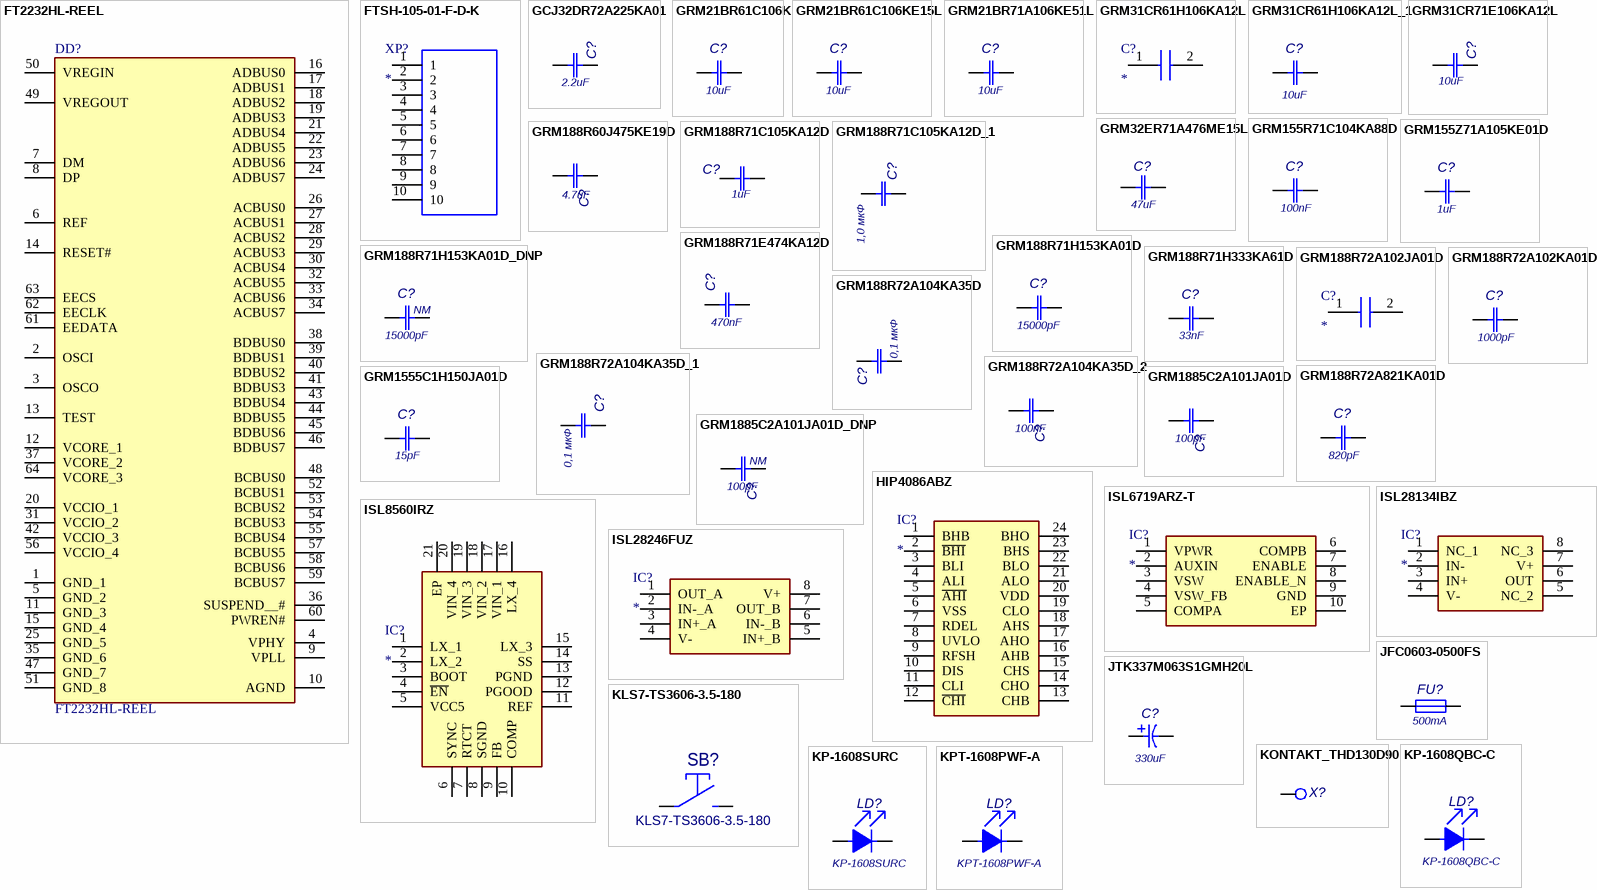
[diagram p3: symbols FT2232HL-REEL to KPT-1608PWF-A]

## FT2232HL-REEL
designator DD?
USB-UART/FIFO; Manufacturer: "FTDI Chip"; TKE: LQFP-64
footprint QFP50P1200X1200X160-64N
pins: 1 GND_1, 2 OSCI, 3 OSCO, 4 VPHY, 5 GND_2, 6 REF, 7 DM, 8 DP, 9 VPLL, 10 AGND, 11 GND_3, 12 VCORE_1, 13 TEST, 14 RESET#, 15 GND_4, 16 ADBUS0, 17 ADBUS1, 18 ADBUS2, 19 ADBUS3, 20 VCCIO_1, 21 ADBUS4, 22 ADBUS5, 23 ADBUS6, 24 ADBUS7, 25 GND_5, 26 ACBUS0, 27 ACBUS1, 28 ACBUS2, 29 ACBUS3, 30 ACBUS4, 31 VCCIO_2, 32 ACBUS5, 33 ACBUS6, 34 ACBUS7, 35 GND_6, 36 SUSPEND__#, 37 VCORE_2, 38 BDBUS0, 39 BDBUS1, 40 BDBUS2, 41 BDBUS3, 42 VCCIO_3, 43 BDBUS4, 44 BDBUS5, 45 BDBUS6, 46 BDBUS7, 47 GND_7, 48 BCBUS0, 49 VREGOUT, 50 VREGIN, 51 GND_8, 52 BCBUS1, 53 BCBUS2, 54 BCBUS3, 55 BCBUS4, 56 VCCIO_4, 57 BCBUS5, 58 BCBUS6, 59 BCBUS7, 60 PWREN#, 61 EEDATA, 62 EECLK, 63 EECS, 64 VCORE_3

## FTSH-105-01-F-D-K
designator XP?
Connector; Manufacturer_Name: SAMTEC; Manufacturer_Part_Number: FTSH-105-01-F-D-K; Manufacturer: "Samtec"
footprint FTSH-105-XX-YYY-D-K
pins: 1, 2, 3, 4, 5, 6, 7, 8, 9, 10

## GCJ32DR72A225KA01
designator C?  value 2.2uF  (hidden comment: GCJ32DR72A225KA01)
1210 X7R 2,2uF±10% 100V; Manufacturer: "Murata"; Tolerance: ±10%; NOM: 1210 X7R 2.2uF ±10% 100V; Value Ru: 2,2 мкФ
footprint CAPC3225X200N
pins: 1, 2

## GRM21BR61C106K
designator C?, comment value 10uF  (hidden comment: GRM21BR71A106KE51L)
0805 X5R 10uF±10% 16V; Manufacturer: "Murata"; TKE: 0805 X7R; Tolerance: ±10%; Power_Voltage: 10V; NOM: 0805 X7R 10uF ±10% 10V; Value Ru: 10 мкФ
footprint CAPC2012X125N
pins: 1, 2

## GRM21BR61C106KE15L
designator C?  value 10uF  (hidden comment: GRM21BR61C106KE15L)
0805 X5R 10uF±10% 16V; Manufacturer: "Murata"; Tolerance: ±10%; Value Ru: 10 мкФ
footprint CAPC2012X125N
pins: 1, 2

## GRM21BR71A106KE51L
designator C?  value 10uF  (hidden comment: GRM21BR71A106KE51L)
0805 X7R 10uF±10% 10V; Manufacturer: "Murata"; Tolerance: ±10%; Value Ru: 10 мкФ
footprint CAP0805 (SMD Ceramic Chip Capacitor 0805,  metric 2012)
footprint CAPC2012X125N
pins: 1, 2

## GRM31CR61H106KA12L
designator C?
Capacitor; Manufacturer_Name: Murata Electronics; Manufacturer_Part_Number: GRM31CR61H106KA12L
footprint CAPC3216X180N
pins: 1, 2

## GRM31CR61H106KA12L_1
designator C?, comment value 10uF  (hidden comment: GRM31CR61H106KA12L)
1206 X5R 10uF±10% 50V; Manufacturer: "Murata"; Tolerance: ±10%; Value Ru: 10 мкФ
footprint CAPC3216X180N
pins: 1, 2

## GRM31CR71E106KA12L
designator C?  value 10uF  (hidden comment: GRM31CR71E106KA12L)
1206 X7R 10uF±10% 25V; Manufacturer: "Murata"; Tolerance: ±10%; Value Ru: 10 мкФ
footprint CAPC3216X160N
pins: 1, 2

## GRM32ER71A476ME15L
designator C?  value 47uF  (hidden comment: GRM32ER71A476ME15L)
1210 X7R 47uF±20% 10V; Manufacturer: "Murata"; Tolerance: ±20%; Value Ru: 47 мкФ
footprint CAPC3225X250N
pins: 1, 2

## GRM155R71C104KA88D
designator C?  value 100nF  (hidden comment: GRM155R71C104KA88D)
0402 X7R  0,1 uF±10% 16V; Manufacturer: "Murata"; Tolerance: ±10%; Power_Voltage: 16В; NOM: 0402 X7R 100nF ±10% 16В; Value Ru: 0,1 мкФ
footprint CAPC1005X50N
footprint CAPC1005X50N_small(PAD70X65)
pins: 1, 2

## GRM155Z71A105KE01D
designator C?  value 1uF  (hidden comment: GRM155Z71A105KE01D)
0402 X7R  1 uF±10% 10V; Manufacturer: "Murata"; Tolerance: ±10%; Power_Voltage: 10В; NOM: 0402 X7R 1uF ±10% 10В; Value Ru: 1 мкФ
footprint CAPC1005X50N
footprint CAPC1005X50N_small(PAD70X65)
pins: 1, 2

## GRM188R60J475KE19D
designator C?  value 4.7uF  (hidden comment: GRM188R60J475KE19D)
0603 X5R 4,7uF ±10% 6,3V; Manufacturer: "Murata"; Power_Voltage: 6,3V; NOM: 0603 X5R 4.7uF ±10% 6,3V; Value Ru: 4.7 мкФ
footprint CAPC1608X80N
pins: 1, 2

## GRM188R71C105KA12D
designator C?  value 1uF  (hidden comment: GRM188R71C105KA12D)
0603 X7R 1,0 uF±10% 16V; Manufacturer: "Murata"; Tolerance: ±10%; NOM: 0603 X7R 1uF ±10% 16V; Value Ru: 1,0 мкФ
footprint CAPC1608X80N
pins: 1, 2

## GRM188R71C105KA12D_1
designator C?  value 1,0 мкФ
0603 X7R 1,0 мкФ ±10% 16В; ManufacturerPartNumber: GRM188R71C105KA12D; Manufacturer: "Murata"
footprint CAPC1608X80N
pins: 1, 2

## GRM188R71E474KA12D
designator C?  value 470nF  (hidden comment: GRM188R71E474KA12D)
0603 X7R 470nF±10% 25V; Manufacturer: "Murata"; Tolerance: ±10%; Value Ru: 0,47 мкФ
footprint CAPC1608X80N
pins: 1, 2

## GRM188R71H153KA01D
designator C?  value 15000pF  (hidden comment: GRM188R71H153KA01D)
0603 X7R 15000pF±10% 50V; Manufacturer: "Murata"; Tolerance: ±10%; Value Ru: 15000 пФ
footprint CAPC1608X80N
pins: 1, 2

## GRM188R71H153KA01D_DNP
designator C?, comment value 15000pF  Примечание: NM  (hidden comment: GRM188R71H153KA01D)
0603 X7R 15000pF±10% 50V; Manufacturer: "Murata"; Tolerance: ±10%; Value Ru: 15000 пФ
footprint CAPC1608X80N
pins: 1, 2

## GRM188R71H333KA61D
designator C?  value 33nF  (hidden comment: GRM188R71H333KA61D)
0603 X7R 33nF±10% 50V; Manufacturer: "Murata"; Tolerance: ±10%; Value Ru: 33000 пФ
footprint CAPC1608X80N
pins: 1, 2

## GRM188R72A102JA01D
designator C?
Capacitor; Manufacturer_Name: Murata Electronics; Manufacturer_Part_Number: GRM188R72A102JA01D
footprint CAPC1608X90N
pins: 1, 2

## GRM188R72A102KA01D
designator C?  Value Eng: 1000pF
0603 X7R 1000 пФ ±10% 100В; ManufacturerPartNumber: GRM188R72A102KA01D; Manufacturer: "Murata"; Value: 1000 пФ
footprint CAPC1608X80N
pins: 1, 2

## GRM188R72A104KA35D
designator C?  value 0,1 мкФ  (hidden comment: GRM188R72A104KA35D)
0603 X7R 0,1 мкФ ±10% 100В; Manufacturer: "Murata"
footprint CAPC1608X80N
pins: 1, 2

## GRM188R72A104KA35D_1
designator C?, comment value 0,1 мкФ  (hidden comment: GRM188R72A104KA35D)
0603 X7R 0,1 мкФ ±10% 100В; Manufacturer: "Murata"
footprint CAPC1608X80N
pins: 1, 2

## GRM188R72A104KA35D_2
designator C?, comment value 100nF  (hidden comment: GRM188R72A104KA35D)
0603 X7R 0,1uF±10% 100V; Manufacturer: "Murata"; Tolerance: ±10%; NOM: 0603 X7R 100nF ±10% 100V; Value Ru: 0,1 мкФ
footprint CAPC1608X80N
pins: 1, 2

## GRM188R72A821KA01D
designator C?  value 820pF  (hidden comment: GRM188R72A821KA01D)
0603 X7R 820pF±10% 100V; Manufacturer: "Murata"; Tolerance: ±10%; Value Ru: 820 пФ
footprint CAPC1608X80N
pins: 1, 2

## GRM1555C1H150JA01D
designator C?  value 15pF  (hidden comment: GRM1555C1H150JA01D)
0402 COG 15 pF±5% 50V; Manufacturer: "Murata"; Tolerance: ±5%; Value Ru: 15 пФ
footprint CAPC1005X50N
pins: 1, 2

## GRM1885C2A101JA01D
designator C?  value 100pF  (hidden comment: GRM1885C2A101JA01D)
0603 C0G 100pF±5% 100V; Manufacturer: "Murata"; Tolerance: ±5%; Value Ru: 100 пФ
footprint CAPC1608X80N
pins: 1, 2

## GRM1885C2A101JA01D_DNP
designator C?, comment value 100pF  Примечание: NM  (hidden comment: GRM1885C2A101JA01D)
0603 C0G 100pF±5% 100V; Manufacturer: "Murata"; Tolerance: ±5%; Value Ru: 100 пФ
footprint CAPC1608X80N
pins: 1, 2

## HIP4086ABZ
designator IC?
Integrated Circuit; Manufacturer_Name: Renesas Electronics; Manufacturer_Part_Number: HIP4086ABZ
footprint SOIC127P1032X265-24N
pins: 1 BHB, 2 ~{BHI}, 3 BLI, 4 ALI, 5 ~{AHI}, 6 VSS, 7 RDEL, 8 UVLO, 9 RFSH, 10 DIS, 11 CLI, 12 ~{CHI}, 13 CHB, 14 CHO, 15 CHS, 16 AHB, 17 AHO, 18 AHS, 19 CLO, 20 VDD, 21 ALO, 22 BLO, 23 BHS, 24 BHO

## ISL6719ARZ-T
designator IC?
Integrated Circuit; Manufacturer_Name: Renesas Electronics; Manufacturer_Part_Number: ISL6719ARZ-T
footprint ISL6719ARZT
pins: 1 VPWR, 2 AUXIN, 3 VSW, 4 VSW_FB, 5 COMPA, 6 COMPB, 7 ENABLE, 8 ENABLE_N, 9 GND, 10 EP

## ISL8560IRZ
designator IC?
Integrated Circuit; Manufacturer_Name: Renesas Electronics; Manufacturer_Part_Number: ISL8560IRZ
footprint QFN80P600X600X100-21N
pins: 1 LX_1, 2 LX_2, 3 BOOT, 4 ~{EN}, 5 VCC5, 6 SYNC, 7 RTCT, 8 SGND, 9 FB, 10 COMP, 11 REF, 12 PGOOD, 13 PGND, 14 SS, 15 LX_3, 16 LX_4, 17 VIN_1, 18 VIN_2, 19 VIN_3, 20 VIN_4, 21 EP

## ISL28134IBZ
designator IC?
Integrated Circuit; Manufacturer_Name: Renesas Electronics; Manufacturer_Part_Number: ISL28134IBZ
footprint SOIC127P600X175-8N
pins: 1 NC_1, 2 IN-, 3 IN+, 4 V-, 5 NC_2, 6 OUT, 7 V+, 8 NC_3

## ISL28246FUZ
designator IC?
Integrated Circuit; Manufacturer_Name: Renesas Electronics; Manufacturer_Part_Number: ISL28246FUZ
footprint SOP65P490X110-8N
pins: 1 OUT_A, 2 IN-_A, 3 IN+_A, 4 V-, 5 IN+_B, 6 IN-_B, 7 OUT_B, 8 V+

## JFC0603-0500FS
designator FU?  value 500mA  (hidden comment: JFC0603-0500FS)
Fuse 500mA 32V 0603; Manufacturer: "JDT Fuse Industrial"; MARK: F
footprint RESC1608X45N
pins: 1, 2

## JTK337M063S1GMH20L
designator C?  value 330uF  (hidden comment: JTK337M063S1GMH20L)
330 uF±20% 63V; Manufacturer: "Jamicon"; Tolerance: ±20%; Примечание: 10mm x 20mm Electrolytic Capacitors; Value Ru: 330 мкФ
footprint CAPPRD500W60D1275H2200
pins: 1, 2

## KLS7-TS3606-3.5-180
designator SB?
Kind of Tactile Switch; Manufacturer: "KLS"; ESKDname: Кнопка тактовая KLS7-TS3606-3.5-180
footprint KLS7-TS3606-3.5-180 (Tact Switch 3x6)
pins: 1, 2

## KONTAKT_THD130D90
designator X?  (value not drawn)  (no BOM)
footprint PAD_PXEFX130X130XD90
pins: 1 X

## KP-1608QBC-C
designator LD?
0603 Led Diod Blue SMD; Manufacturer: "Kingbright"; TKE: 0603
footprint KPT1608X16X08X75N
pins: 1, 2

## KP-1608SURC
designator LD?
0603 LED Diod SMD Red; Manufacturer: "Kingbright"; TKE: 0603
footprint KPT1608X16X08X75N
pins: 1, 2

## KPT-1608PWF-A
designator LD?
0603 LED Diod SMD White; Manufacturer: "Kingbright"; TKE: 0603
footprint KPT1608X16X08X75N
footprint KPT1608X16X08X75N_LINE
pins: 1, 2

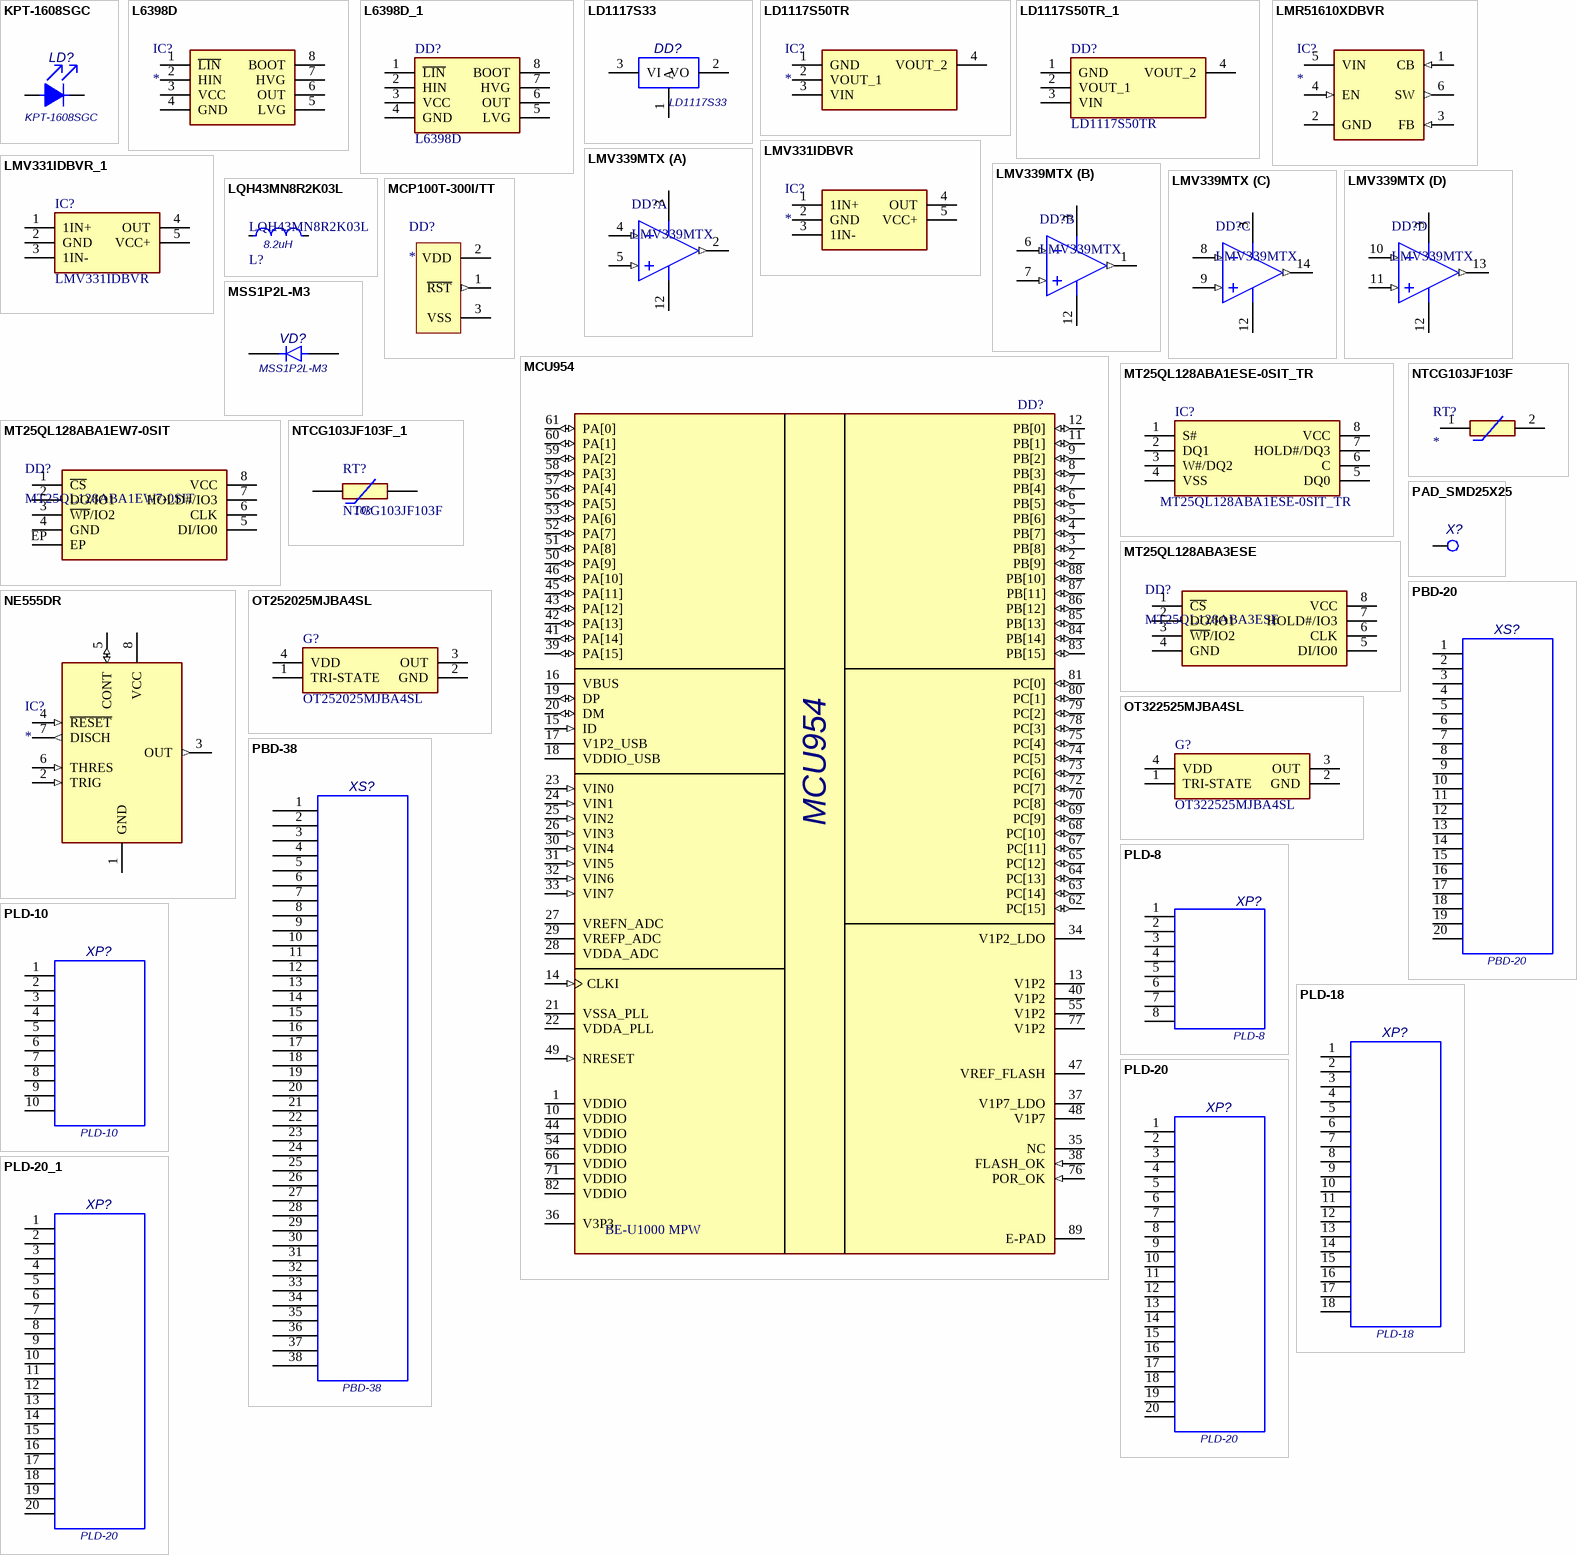
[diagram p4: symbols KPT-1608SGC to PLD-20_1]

## KPT-1608SGC
designator LD?
0603 LED Diod SMD Green; Manufacturer: "Kingbright"; TKE: 0603
footprint KPT1608X16X08X75N
footprint KPT1608X16X08X75N_LINE
pins: 1, 2

## L6398D
designator IC?
Integrated Circuit; Manufacturer_Name: STMicroelectronics; Manufacturer_Part_Number: L6398D
footprint SOIC127P600X175-8N
pins: 1 ~{LIN}, 2 HIN, 3 VCC, 4 GND, 5 LVG, 6 OUT, 7 HVG, 8 BOOT

## L6398D_1
designator DD?, comment L6398D
High voltage high and low-side driver; Manufacturer_Name: STMicroelectronics; Manufacturer: "STMicroelectronics"; TKE: SO-8
footprint SOIC127P600X175-8N
footprint SOIC127P600X175-8N
pins: 1 ~{LIN}, 2 HIN, 3 VCC, 4 GND, 5 LVG, 6 OUT, 7 HVG, 8 BOOT

## LD1117S33
designator DD?
LDO voltage regulator; Manufacturer: "STMicroelectronics"; TKE: SOT-223
footprint SOT230P650X350X180-4N(SOT223) (SOT223, 4-Leads, Body 6.50x7.00mm (avg), Pitch 2.30mm, IPC Medium Density)
pins: 1 A, 2 VO, 3 VI

## LD1117S50TR
designator IC?
Integrated Circuit; Manufacturer_Name: STMicroelectronics; Manufacturer_Part_Number: LD1117S50TR
footprint SOT230P700X190-4N
pins: 1 GND, 2 VOUT_1, 3 VIN, 4 VOUT_2

## LD1117S50TR_1
designator DD?, comment LD1117S50TR
LDO voltage regulator 5V 0.8A; Manufacturer: "STMicroelectronics"; Manufacturer_Name: STMicroelectronics; TKE: SOT-223
footprint SOT230P700X190-4N
pins: 1 GND, 2 VOUT_1, 3 VIN, 4 VOUT_2

## LMR51610XDBVR
designator IC?
Integrated Circuit; Manufacturer_Name: Texas Instruments; Manufacturer_Part_Number: LMR51610XDBVR
footprint SOT95P280X145-6N
pins: 1 CB (in), 2 GND (power), 3 FB (in), 4 EN (in), 5 VIN (power), 6 SW (out)

## LMV331IDBVR
designator IC?
Integrated Circuit; Manufacturer_Name: Texas Instruments; Manufacturer_Part_Number: LMV331IDBVR
footprint SOT95P280X145-5N
pins: 1 1IN+, 2 GND, 3 1IN-, 4 OUT, 5 VCC+

## LMV331IDBVR_1
designator IC?, comment LMV331IDBVR
Integrated Circuit; Manufacturer_Name: Texas Instruments
footprint SOT95P280X145-5N
pins: 1 1IN+, 2 GND, 3 1IN-, 4 OUT, 5 VCC+

## LMV339MTX
designator DD?
Quad General Purpose, Low Voltage, Tiny Pack Comparator, 14-pin TSSOP; Manufacturer: "Texas Instruments"; PackageTopMarking: NSUZXYTT*LMV339*MT; PowerWise: Y; TKE: TSSOP 14
footprint PW0014A_L (SOP, 14-Leads, Body 5.1x4.5mm, Pitch 0.65mm, IPC High Density)
footprint PW0014A_M (SOP, 14-Leads, Body 5.1x4.5mm, Pitch 0.65mm, IPC Low Density)
footprint PW0014A_N (SOP, 14-Leads, Body 5.1x4.5mm, Pitch 0.65mm, IPC Medium Density)
pins on every part: 3 V+ (power), 12 V- (power)
part A pins: 2 OUTA (out), 4 INA- (in), 5 INA+ (in)
part B pins: 1 OUTB (out), 6 INB- (in), 7 INB+ (in)
part C pins: 8 INC- (in), 9 INC+ (in), 14 OUTC (out)
part D pins: 10 IND- (in), 11 IND+ (in), 13 OUTD (out)

## LQH43MN8R2K03L
designator L?  value 8.2uH
Wire Wound Ferrite Inductor for General Circuits 8.2μH ±10% 0.56Ω 450mA 1812; Manufacturer: "Murata"; Q Factor: 30; Shielding: Unshielded; DC Resistance (DCR): 560mR; Test Frequency: 1MHz; Self Resonant Frequency: 27MHz; Value Ru: 8.2 мкГн; TKE: 1812
footprint FP-LQH43CN_03-MFG
pins: 1, 2

## MCP100T-300I/TT
designator DD?
Supervisor Integrated Circuit
footprint SOT-23-TT3_L (SOT23, 3-Leads, Body 2.9x1.3mm, Pitch 0.95mm, Lead Span 2.4mm, IPC High Density)
pins: 1 ~{RST} (out), 2 VDD (power), 3 VSS (power)

## MCU954
designator DD?, comment BE-U1000 MPW
Microcontroller BE-U1000 MPW; Manufacturer: "Baikal Electronics"; TKE: QFN 88
footprint QFNWB10X10-88L-AL
pins: 1 VDDIO (power), 2 PB[9] (io), 3 PB[8] (io), 4 PB[7] (io), 5 PB[6] (io), 6 PB[5] (io), 7 PB[4] (io), 8 PB[3] (io), 9 PB[2] (io), 10 VDDIO (power), 11 PB[1] (io), 12 PB[0] (io), 13 V1P2 (power), 14 CLKI (in), 15 ID (in), 16 VBUS (power), 17 V1P2_USB (power), 18 VDDIO_USB (power), 19 DP (io), 20 DM (io), 21 VSSA_PLL (power), 22 VDDA_PLL (power), 23 VIN0 (in), 24 VIN1 (in), 25 VIN2 (in), 26 VIN3 (in), 27 VREFN_ADC (power), 28 VDDA_ADC (power), 29 VREFP_ADC (power), 30 VIN4 (in), 31 VIN5 (in), 32 VIN6 (in), 33 VIN7 (in), 34 V1P2_LDO (power), 35 NC, 36 V3P3 (power), 37 V1P7_LDO (power), 38 FLASH_OK (in), 39 PA[15] (io), 40 V1P2 (power), 41 PA[14] (io), 42 PA[13] (io), 43 PA[12] (io), 44 VDDIO (power), 45 PA[11] (io), 46 PA[10] (io), 47 VREF_FLASH (power), 48 V1P7 (power), 49 NRESET (in), 50 PA[9] (io), 51 PA[8] (io), 52 PA[7] (io), 53 PA[6] (io), 54 VDDIO (power), 55 V1P2 (power), 56 PA[5] (io), 57 PA[4] (io), 58 PA[3] (io), 59 PA[2] (io), 60 PA[1] (io), 61 PA[0] (io), 62 PC[15] (io), 63 PC[14] (io), 64 PC[13] (io), 65 PC[12] (io), 66 VDDIO (power), 67 PC[11] (io), 68 PC[10] (io), 69 PC[9] (io), 70 PC[8] (io), 71 VDDIO (power), 72 PC[7] (io), 73 PC[6] (io), 74 PC[5] (io), 75 PC[4] (io), 76 POR_OK (in), 77 V1P2 (power), 78 PC[3] (io), 79 PC[2] (io), 80 PC[1] (io), 81 PC[0] (io), 82 VDDIO (power), 83 PB[15] (io), 84 PB[14] (io), 85 PB[13] (io), 86 PB[12] (io), 87 PB[11] (io), 88 PB[10] (io), 89 E-PAD (power)

## MSS1P2L-M3
designator VD?
Schottky Diod; Manufacturer: "Vishay"
footprint MicroSMP27X14X7
pins: 1 C, 2 A

## MT25QL128ABA1ESE-0SIT_TR
designator IC?
Integrated Circuit; Manufacturer_Name: Micron; Manufacturer_Part_Number: MT25QL128ABA1ESE-0SIT TR
footprint SOIC127P790X216-8N
pins: 1 S#, 2 DQ1, 3 W#/DQ2, 4 VSS, 5 DQ0, 6 C, 7 HOLD#/DQ3, 8 VCC

## MT25QL128ABA1EW7-0SIT
designator DD?
FLASH 128MBIT SPI 8WPDFN; Manufacturer: "Micron"
footprint W-PDFN-8(5x6)
pins: 1 ~{CS}, 2 DO/IO1, 3 ~{WP}/IO2, 4 GND, 5 DI/IO0, 6 CLK, 7 HOLD#/IO3, 8 VCC, EP

## MT25QL128ABA3ESE
designator DD?
NOR Flash Serial (SPI, Dual SPI, Quad SPI) 3V/3.3V 128M-bit 128M; Manufacturer: "Micron"; Manufacturer_Part_Number: MT25QL128ABA1ESE-0SIT TR
footprint SOIC127P790X216-8N
pins: 1 ~{CS}, 2 DO/IO1, 3 ~{WP}/IO2, 4 GND, 5 DI/IO0, 6 CLK, 7 HOLD#/IO3, 8 VCC

## NE555DR
designator IC?
Integrated Circuit; Manufacturer_Name: Texas Instruments; Manufacturer_Part_Number: NE555DR
footprint SOIC127P600X175-8N
pins: 1 GND (power), 2 TRIG (in), 3 OUT (out), 4 ~{RESET} (in), 5 CONT (io), 6 THRES (in), 7 DISCH (out), 8 VCC (power)

## NTCG103JF103F
designator RT?
Thermistor; Manufacturer_Name: TDK; Manufacturer_Part_Number: NTCG103JF103F
footprint THRMC1005X55N
pins: 1, 2

## NTCG103JF103F_1
designator RT?, comment NTCG103JF103F  value 10k
Thermistor NTC 0402 10 kOhms±1% 0,1W; Manufacturer: "TDK"; TKE: 0402; Value Ru: 10 кОм; Tolerance: ±1%; NOM: 0402 10k ±1% 0,1W; Power_Voltage: 0,1W
footprint THRMC1005X55N
pins: 1, 2

## OT252025MJBA4SL
designator G?
3.3V ±10ppm 5mA ±20ppm CMOS 25MHz  Oscillator; Manufacturer: "YXC"; Manufacturer_Part_Number: OT322525MJBA4SL; TKE: SMD3225-4P
footprint Crystal_4-SMD_2.5x2.0
pins: 1 TRI-STATE, 2 GND, 3 OUT, 4 VDD

## OT322525MJBA4SL
designator G?
3.3V ±10ppm 5mA ±20ppm CMOS 25MHz  Oscillator; Manufacturer: "YXC"; TKE: SMD3225-4P
footprint OT322525MJBA4SL
pins: 1 TRI-STATE, 2 GND, 3 OUT, 4 VDD

## PAD_SMD25X25
designator X?  (value not drawn)  (no BOM)
footprint PAD_SMD25X25
footprint PAD_SMD25X25
pins: 1 X

## PBD-20
designator XS?
2.54 pitch, 2 rows, 8.54 height; ManufacturerPartNumber: PLD-20; Manufacturer: "ТД Бурый медведь"
footprint DS1023210SF11
pins: 1, 2, 3, 4, 5, 6, 7, 8, 9, 10, 11, 12, 13, 14, 15, 16, 17, 18, 19, 20

## PBD-38
designator XS?
2.54 pitch, 2 rows, 8.54 height; ManufacturerPartNumber: PLD-38; Manufacturer: "ТД Бурый медведь"
footprint DS1023219SF11
pins: 1, 2, 3, 4, 5, 6, 7, 8, 9, 10, 11, 12, 13, 14, 15, 16, 17, 18, 19, 20, 21, 22, 23, 24, 25, 26, 27, 28, 29, 30, 31, 32, 33, 34, 35, 36, 37, 38

## PLD-8
designator XP?
2.54 pitch, 2 rows, 8.54 height; Manufacturer: "ТД Бурый медведь"
footprint PLD8-254PX1001X254X854N
pins: 1, 2, 3, 4, 5, 6, 7, 8

## PLD-10
designator XP?
2.54 pitch, 2 rows, 8.54 height; Manufacturer: "ТД Бурый медведь"
footprint PLD10-254PX1278X254X854N
pins: 1, 2, 3, 4, 5, 6, 7, 8, 9, 10

## PLD-18
designator XP?
2.54 pitch, 2 rows, 8.54 height; Manufacturer: "ТД Бурый медведь"
footprint PLD18-254PX2294X254X854N
pins: 1, 2, 3, 4, 5, 6, 7, 8, 9, 10, 11, 12, 13, 14, 15, 16, 17, 18

## PLD-20
designator XP?
2.54 pitch, 2 rows, 8.54 height; Manufacturer: "ТД Бурый медведь"
footprint PLD20-254PX2548X254X854N
pins: 1, 2, 3, 4, 5, 6, 7, 8, 9, 10, 11, 12, 13, 14, 15, 16, 17, 18, 19, 20

## PLD-20_1
designator XP?, comment PLD-20
2.54 pitch, 2 rows, 8.54 height; Manufacturer: "ТД Бурый медведь"
footprint PLD20-254PX2548X254X854N
pins: 1, 2, 3, 4, 5, 6, 7, 8, 9, 10, 11, 12, 13, 14, 15, 16, 17, 18, 19, 20

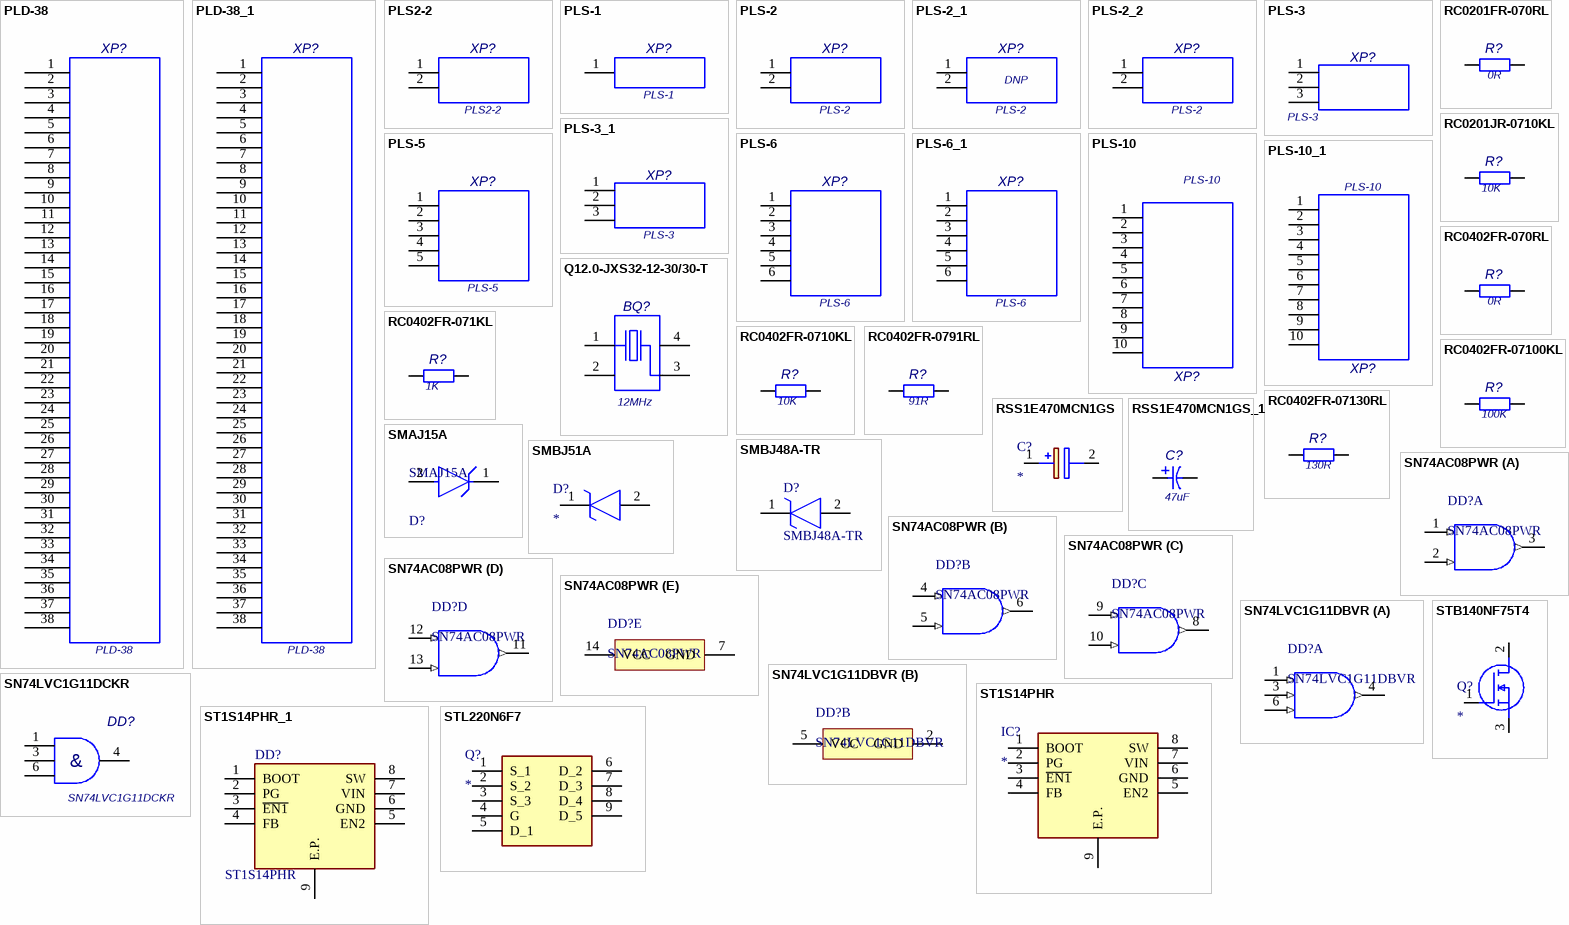
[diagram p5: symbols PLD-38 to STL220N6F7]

## PLD-38
designator XP?
2.54 pitch, 2 rows, 8.54 height; Manufacturer: "ТД Бурый медведь"
footprint PLD38-254PX4834X254X854N
pins: 1, 2, 3, 4, 5, 6, 7, 8, 9, 10, 11, 12, 13, 14, 15, 16, 17, 18, 19, 20, 21, 22, 23, 24, 25, 26, 27, 28, 29, 30, 31, 32, 33, 34, 35, 36, 37, 38

## PLD-38_1
designator XP?, comment PLD-38
2.54 pitch, 2 rows, 8.54 height; Manufacturer: "ТД Бурый медведь"
footprint PLD38-254PX4834X254X854N
pins: 1, 2, 3, 4, 5, 6, 7, 8, 9, 10, 11, 12, 13, 14, 15, 16, 17, 18, 19, 20, 21, 22, 23, 24, 25, 26, 27, 28, 29, 30, 31, 32, 33, 34, 35, 36, 37, 38

## PLS2-2
designator XP?
2.0 pitch, DIP, 1 rows, 5.5 height; Manufacturer: "ТД Бурый медведь"
footprint PLS2-2-200PX400X240X550
pins: 1, 2

## PLS-1
designator XP?
2.54 pitch, 1 rows, 8.54 height; Manufacturer: "ТД Бурый медведь"
footprint PLS-1
pins: 1

## PLS-2
designator XP?
2.54 pitch, 1 rows, 8.54 height; Manufacturer: "ТД Бурый медведь"
footprint PLS2-254PX50X25X854N
pins: 1, 2

## PLS-2_1
designator XP?, comment PLS-2  Примечание: DNP
2.54 pitch, 1 rows, 8.54 height; Manufacturer: "ТД Бурый медведь"
footprint PLS2-254PX50X25X854N
pins: 1, 2

## PLS-2_2
designator XP?, comment PLS-2
2.54 pitch, 1 rows, 8.54 height; Manufacturer: "ТД Бурый медведь"
footprint PLS2-254PX50X25X854N
pins: 1, 2

## PLS-3
designator XP?
2.54 pitch, 1 rows, 8.54 height; Manufacturer: "ТД Бурый медведь"
footprint PLS3-254PX76X25X854N
pins: 1, 2, 3

## PLS-3_1
designator XP?, comment PLS-3
2.54 pitch, 1 rows, 8.54 height; Manufacturer: "ТД Бурый медведь"
footprint PLS3-254PX76X25X854N
pins: 1, 2, 3

## PLS-5
designator XP?
2.54 pitch, 1 rows, 8.54 height; Manufacturer: "ТД Бурый медведь"
footprint PLS5-254PX127X25X854N
pins: 1, 2, 3, 4, 5

## PLS-6
designator XP?
2.54 pitch, 1 rows, 8.54 height; Manufacturer: "ТД Бурый медведь"
footprint PLS6-254PX152X25X854N
pins: 1, 2, 3, 4, 5, 6

## PLS-6_1
designator XP?, comment PLS-6
2.54 pitch, 1 rows, 8.54 height; Manufacturer: "ТД Бурый медведь"
footprint PLS6-254PX152X25X854N
pins: 1, 2, 3, 4, 5, 6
